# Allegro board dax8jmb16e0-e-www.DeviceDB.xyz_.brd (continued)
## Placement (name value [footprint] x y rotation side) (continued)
R623  33/F_4  [R0402]  49 29.29 270 top
R625  2.2K_2  [R0201]  78.52 125.46 270 top
R626  2.2K_2  [R0201]  77.76 125.46 270 top
R627  60.4/F_4  [R0402]  142.44 103.81 180 bottom
R628  4.7K/F_4  [R0402]  146.34 82.4 90 bottom
R629  *20K/F_4  [R0402]  144.94 82.83 180 bottom
R630  *8.25K/F_4  [R0402]  63.53 127.16 0 bottom
R632  *1K_1%_2  [R0201]  38.44 121.09 90 top
R633  *1K_1%_2  [R0201]  37.55 121.49 0 top
R634  *1K_1%_2  [R0201]  37.3 120.78 180 top
R635  *1K_1%_2  [R0201]  36.43 121.19 90 top
R637  *1K_1%_2  [R0201]  34.17 121.47 180 top
R638  *1K_1%_2  [R0201]  33.13 120.86 180 top
R639  *1K_1%_2  [R0201]  33 121.65 180 top
R640  *1K_1%_2  [R0201]  38.95 110.6 90 top
R641  *1K_1%_2  [R0201]  38.21 110.67 270 top
R642  *1K_1%_2  [R0201]  37.04 110.39 90 top
R643  *1K_1%_2  [R0201]  36.23 110.6 270 top
R644  *1K_1%_2  [R0201]  34.27 110.65 270 top
R645  *1K_1%_2  [R0201]  33.38 110.67 0 top
R646  *1K_1%_2  [R0201]  32.52 110.72 90 top
R647  *1K_1%_2  [R0201]  32.52 109.73 270 top
R648  *0_4  [R0402]  129.42 68.56 90 top
R649  10K_5%_2  [R0201]  154.82 96.73 270 bottom
R651  10K_5%_2  [R0201]  143.11 85.83 0 top
R652  100K_4  [R0402]  146.06 92.36 180 top
R653  100K_4  [R0402]  135.61 70.68 90 top
R654  *20K/F_4  [R0402]  134.56 71.76 270 top
R655  *0_2  [R0201]  132.24 75.43 180 bottom
R656  *0_2  [R0201]  149.21 69.53 180 top
R657  *0_2  [R0201]  125.89 76.36 270 bottom
R659  100K/F_4  [R0402]  153.7 92.03 90 top
R660  100K_4  [R0402]  146.92 69.65 180 top
R2800  240_4  [R0402]  81.95 39.48 90 top
R2801  *0_6/S  [S0603]  119.26 37.27 180 top
R2802  240_4  [R0402]  72.98 45.14 90 top
R2803  240_4  [R0402]  71.97 45.14 90 top
R2804  240_4  [R0402]  72.75 37.01 269.6 top
R2805  240_4  [R0402]  70.95 45.14 90 top
R2806  240_4  [R0402]  74 45.14 90 top
R2807  240_4  [R0402]  75.01 45.14 90 top
R2808  240_4  [R0402]  71.69 37.01 270 top
R2809  240_4  [R0402]  69.93 45.14 90 top
R2810  240_4  [R0402]  73.77 37.01 270 top
R2811  240_4  [R0402]  74.84 37.01 270 top
R2812  1K_1%_2  [R0201]  120.73 39.2 0 top
R2813  2/F_6  [R0603]  119.52 41.36 90 top
R2814  *10K_5%_2  [R0201]  113.11 39.78 180 top
R2815  *10K_5%_2  [R0201]  113.11 40.57 180 top
R2816  *10K_5%_2  [R0201]  92.67 36.91 0 top
R2817  1K_1%_2  [R0201]  120.73 38.46 180 top
R2818  24.9/F_4  [R0402]  117.92 43.11 270 top
R2819  10K_5%_2  [R0201]  114.66 39.78 180 top
R2820  10K_5%_2  [R0201]  114.66 40.57 180 top
R2821  10K_5%_2  [R0201]  92.67 37.7 180 top
R2822  *0_6/S  [S0603]  125.46 37.39 90 top
R2823  *10K_5%_2  [R0201]  190.1 41.25 270 top
R2824  10K_5%_2  [R0201]  190.86 41.84 270 top
R2825  *10K_5%_2  [R0201]  170.65 37.11 90 top
R2826  10K_5%_2  [R0201]  190.64 39.65 270 top
R2827  *10K_5%_2  [R0201]  190.99 40.95 0 top
R2828  10K_5%_2  [R0201]  169.73 37.62 0 top
R2829  240_4  [R0402]  148.78 37.83 270 top
R2830  240_4  [R0402]  147.56 45.12 90 top
R2831  240_4  [R0402]  150.99 45.12 90 top
R2832  240_4  [R0402]  149.84 45.12 90 top
R2833  240_4  [R0402]  150.68 41.61 180 top
R2834  240_4  [R0402]  147.71 37.83 270 top
R2835  240_4  [R0402]  146.41 45.12 90 top
R2836  240_4  [R0402]  150.5 37.93 270 top
R2837  240_4  [R0402]  151.95 38.08 0 top
R2838  240_4  [R0402]  148.7 45.12 90 top
R2839  1K_1%_2  [R0201]  121.83 39.6 180 top
R2840  1K_1%_2  [R0201]  121.83 38.84 0 top
R2841  2/F_6  [R0603]  121.04 41.36 90 top
R2842  24.9/F_4  [R0402]  122.33 41.79 90 top
R3300  10K_5%_2  [R0201]  14.72 100.26 270 top
R3301  10K/F_4  [R0402]  146.13 10.8 180 bottom
R3302  *10K/F_4  [R0402]  147.86 10.8 0 bottom
R3303  *0_4/S  [S0402]  147.86 11.77 180 bottom
R3304  *0_4/S  [S0402]  197.16 22.76 90 bottom
R3305  *0_4/S  [S0402]  174.05 24.9 270 bottom
R3306  *0_4/S  [S0402]  149.23 11.33 270 bottom
R3307  *0_4/S  [S0402]  155.46 21.09 270 bottom
R3309  10K_5%_2  [R0201]  125.59 122.99 0 top
R3310  *0_4  [R0402]  127.14 121.06 0 top
R3311  *0_4/S  [S0402]  48.5 95.28 90 top
R3312  *0_4/S  [S0402]  14.33 102.67 0 top
R3400  1K_1%_2  [R0201]  25.69 124.82 90 top
R3402  *0_4/S  [S0402]  25.79 123.42 90 top
R3404  100K_1%_2  [R0201]  24.6 121.34 90 top
R3405  1K_1%_2  [R0201]  39.61 126.29 270 top
R3408  *0_4/S  [S0402]  27.11 129.29 90 top
R3409  *0_4/S  [S0402]  28.13 129.29 90 top
R3410  100K_1%_2  [R0201]  31.99 122.41 270 top
R3411  *0_6/S  [S0603]  46.03 127.89 0 top
R3412  *100K_4  [R0402]  33.92 128.81 90 top
R3413  *100K_4  [R0402]  32.77 128.81 90 top
R3414  *1K_4  [R0402]  37.42 125.94 180 top
R3415  *1K_4  [R0402]  23.15 120.83 0 top
R3416  10_4  [R0402]  37.42 126.93 0 top
R3417  *0_5%_6/S  [S0603]  41.3 126.41 180 top
R3418  *0_5%_6/S  [S0603]  42.27 124.93 180 top
R3419  *0_5%_6/S  [S0603]  24.29 127.06 270 top
R3420  10K_5%_2  [R0201]  24.34 128.73 0 top
R3421  2.2K_2  [R0201]  32.67 130.66 90 top
R3422  2.2K_2  [R0201]  33.41 130.66 90 top
R3423  2K_1%_4  [R0402]  23.15 121.98 180 top
R3424  47K_1%_4  [R0402]  16.62 114.74 0 top
R3425  *0_4  [R0402]  45.32 124.52 180 top
R3428  470K_4  [R0402]  30.84 132.14 0 top
R3500  *150_5%_4  [R0402]  227.9 77.35 90 bottom
R3501  *150_5%_4  [R0402]  227.9 75.6 90 bottom
R3502  *150_5%_4  [R0402]  229.19 77.96 0 top
R3503  *150_5%_4  [R0402]  227.9 73.82 90 bottom
R3504  *4.7K_4  [R0402]  214.36 82.76 90 top
R3505  *4.7K_4  [R0402]  214.36 85.07 90 top
R3506  *4.7K_4  [R0402]  211.26 87.51 90 bottom
R3507  *4.7K_4  [R0402]  213 83.46 0 top
R3508  *4.7K_4  [R0402]  213.37 85.07 270 top
R3509  5.9K_1%_4  [R0402]  215.35 85.07 270 top
R3510  2.2K_2  [R0201]  227.87 62.29 90 bottom
R3511  2.2K_2  [R0201]  226.73 62.29 90 bottom
R3512  2.2K_2  [R0201]  213.47 94.01 270 top
R3513  2.2K_2  [R0201]  212.4 94.01 270 top
R3600  *0_4/S  [S0402]  225.67 21.64 0 top
R3601  BLM15BB121SN1D(120,300)  [R0402]  225.61 13.39 0 top
R3602  BLM15BB121SN1D(120,300)  [R0402]  225.76 12.43 0 top
R3606  *0_4/S  [S0402]  214.03 14.03 0 top
R3607  22/F_4  [R0402]  212.63 13.47 270 top
R3608  30/F_4  [R0402]  223.86 13.19 0 top
R3609  30/F_4  [R0402]  224.01 12.22 0 top
R3610  200K_4  [R0402]  213.95 7.85 270 top
R3611  22/F_4  [R0402]  213.47 10.17 180 top
R3612  100K_4  [R0402]  222.77 6.61 0 top
R3613  100K_4  [R0402]  216.93 7.57 180 top
R3614  200K_4  [R0402]  219.38 6.85 180 top
R3615  *0_4/S  [S0402]  214.46 11.56 270 top
R3616  1K_1%_2  [R0201]  208.99 7.09 270 top
R3617  1K_1%_2  [R0201]  211.74 6.91 270 top
R3618  *0_8/S  [S0805]  221.04 12.12 0 bottom
R3619  2.2K_2  [R0201]  223.68 11.21 180 top
R3620  100K_4  [R0402]  216.01 16.41 180 top
R3621  *0_4/S  [S0402]  216.01 17.38 0 top
R3622  *0_4  [R0402]  216.8 24.08 0 top
R3623  *10K_1%_4  [R0402]  211.72 18.27 90 top
R3624  *0_4/S  [S0402]  216.81 6.61 180 top
R3627  *0_4/S  [S0402]  227.62 23.86 90 bottom
R4000  2.49K/F_4  [R0402]  196.32 63.05 270 top
R4001  1K_4  [R0402]  186.04 67.72 180 top
R4002  1M_4  [R0402]  192.9 61.52 270 top
R4003  4.3K/F_4  [R0402]  185.96 70.54 90 top
R4004  15K/F_4  [R0402]  189.31 68.56 0 top
R4005  2K/F_4  [R0402]  186.95 70.54 90 top
R4006  *0_4  [R0402]  189.06 72.6 90 top
R4007  330/F_4  [R0402]  227.69 93.15 0 top
R4008  330/F_4  [R0402]  227.95 92.13 180 top
R4012  *0_6/S  [S0603]  231.21 106.67 90 bottom
R4013  *0_6/S  [S0603]  230.34 81.97 180 bottom
R4014  75/F_4  [R0402]  223.63 65.08 180 bottom
R4015  75/F_4  [R0402]  223.63 68.26 180 bottom
R4016  75/F_4  [R0402]  223.58 70.08 180 bottom
R4017  75/F_4  [R0402]  223.4 75.21 90 bottom
R4018  *0_4/S  [S0402]  191.91 60.89 90 top
R4101  100K_1%_2  [R0201]  181.69 89.08 0 top
R4103  *0_4  [R0402]  182.35 87.13 180 top
R4104  10K_5%_2  [R0201]  171.15 89.46 270 top
R4105  *0_4/S  [S0402]  174.79 88.58 180 top
R4106  10K_5%_2  [R0201]  145.27 94.26 180 bottom
R4107  100K_1%_2  [R0201]  171.89 89.46 270 top
R4108  100K_1%_2  [R0201]  166.02 83.42 0 top
R4109  *0_4/S  [S0402]  159.01 81.13 0 bottom
R4110  *0_4/S  [S0402]  159.01 80.17 0 bottom
R4111  100K_1%_2  [R0201]  166.02 82.66 180 top
R4113  *0_5%_4  [R0402]  170.16 95.69 90 bottom
R4114  *0_5%_4  [R0402]  171.18 95.69 90 bottom
R4115  *0_5%_4  [R0402]  171.38 92.74 90 bottom
R4116  1K_1%_2  [R0201]  143.95 94.37 90 bottom
R4117  *10K_5%_2  [R0201]  172.6 89.46 90 top
R4118  22/F_4  [R0402]  168.89 90.02 180 top
R4119  22/F_4  [R0402]  162.43 90.14 180 top
R4120  *0_4  [R0402]  173.34 92.94 90 bottom
R4122  *0_4/S  [S0402]  164.19 83.37 180 top
R4123  *0_4/S  [S0402]  159.78 86.32 0 top
R4136  *4.7K/F_4  [R0402]  177.5 85.35 0 top
R4137  10K/F_4  [R0402]  175.75 85.43 0 top
R4138  *75K_1%_4  [R0402]  175.27 86.54 180 top
R4139  75K/F_4  [R0402]  183.24 89.08 180 top
R4140  *0_4  [R0402]  174.81 87.58 0 top
R4141  100K_1%_4  [R0402]  179.23 85.35 180 top
R4142  *0_6/S  [S0603]  179.31 92.61 0 top
R4143  20K/F_4  [R0402]  167.54 90.1 90 top
R4144  *20K/F_4  [R0402]  170.62 90.88 0 top
R4145  *0_4/S  [S0402]  162.79 87.32 180 top
R4146  *200K_1%_4  [R0402]  162.81 86.08 0 top
R4147  10K_5%_2  [R0201]  144.25 86.67 270 top
R4200  *0_6/S  [S0603]  189.31 81.03 0 top
R4202  *0_4/S  [S0402]  204.81 76.64 180 top
R4203  10K_5%_2  [R0201]  191.04 82.35 270 bottom
R4209  *0_4/S  [S0402]  193.25 82.76 90 bottom
R4210  *10K_5%_2  [R0201]  191.93 82.35 270 bottom
R4212  0_4*  [R0402]  190.05 72.6 270 top
R4213  *0_4  [R0402]  191.19 83.44 90 top
R4214  *10K_5%_2  [R0201]  193.78 71.94 270 top
R4215  *0_4  [R0402]  195.11 78.16 270 top
R4222  *47K/F_4  [R0402]  204.71 66.1 180 bottom
R4223  *0_4  [R0402]  218.3 57.59 0 bottom
R4225  *100K_4  [R0402]  206.22 66.45 90 bottom
R4235  100K_1%_2  [R0201]  194.55 79.43 0 top
R4240  *100K_1%_2  [R0201]  198.48 79.81 270 top
R4242  *0_4  [R0402]  204.81 77.68 0 top
R4245  *0_4/S  [S0402]  200.4 82.46 180 bottom
R4246  *47K/F_4  [R0402]  204.68 78.75 180 top
R4247  *0_4/S  [S0402]  189.47 76.38 0 top
R4248  *0_4/S  [S0402]  189.47 75.42 0 top
R4249  10K_5%_2  [R0201]  207.15 65.94 45 top
R4250  10K_5%_2  [R0201]  205.88 64.01 270 top
R4251  0_4  [R0402]  205.78 63.01 180 top
R4252  0_4  [R0402]  209.18 60.13 270 top
R4253  0_4  [R0402]  205.77 62.03 180 top
R4300  *0_4  [R0402]  204.3 7.37 90 bottom
R4301  0_4  [R0402]  203.98 14.01 270 bottom
R4302  0_4  [R0402]  208.31 16.21 0 top
R4303  *0_5%_4  [R0402]  203.78 15.44 180 bottom
R4304  0_4  [R0402]  208.31 17.48 0 top
R4305  10K/F_4  [R0402]  206.97 21.19 0 top
R4306  *0_4  [R0402]  206.97 22.15 180 top
R4307  *0_4  [R0402]  206.61 23.55 90 top
R4308  0_4  [R0402]  210.36 12.04 0 top
R4309  0_4  [R0402]  210.36 13.06 0 top
R4310  *0_6/S  [S0603]  203.34 9.63 270 bottom
R4700  1M/F_4  [R0402]  214.49 54.64 0 top
R4702  *0_4  [R0402]  215.48 49.84 180 top
R4704  2.2K_2  [R0201]  202.96 62.55 180 top
R4705  2.2K_2  [R0201]  202.96 61.82 180 top
R4706  100K_1%_2  [R0201]  145.02 87.18 180 bottom
R4707  *300_4  [R0402]  205.22 45.7 270 top
R4708  300_4  [R0402]  206.18 45.67 270 top
R4709  4.7_5%_4  [R0402]  201.97 59.59 270 top
R4710  300_4  [R0402]  197.54 42.52 0 top
R4711  4.7_5%_4  [R0402]  204.98 59.59 270 top
R4712  300_4  [R0402]  193.63 49.28 180 top
R4713  4.7_5%_4  [R0402]  204 59.59 270 top
R4714  43_4  [R0402]  213.34 52.48 0 top
R4715  *0_4/S  [S0402]  195.16 55.84 0 top
R4716  *0_6/S  [S0603]  200.92 45.22 225 top
R4717  10K_5%_2  [R0201]  197.09 48.29 0 top
R4718  10K_5%_2  [R0201]  197.11 47.05 0 top
R4719  2.2/F_6  [R0603]  197.75 40.7 270 top
R4720  10K_5%_2  [R0201]  216.11 47.17 180 top
R4721  10K_5%_2  [R0201]  211.21 48.71 180 top
R4722  10K_5%_2  [R0201]  216.11 47.91 180 top
R4723  2.2/F_6  [R0603]  213.8 62.13 0 top
R4724  2.2K_2  [R0201]  198.05 56.34 270 top
R4725  2.2K_2  [R0201]  197.34 56.34 270 top
R4726  2.2K_2  [R0201]  213.22 53.88 270 top
R4727  2.2K_2  [R0201]  214.66 53.78 0 top
R4728  10K_5%_2  [R0201]  212.71 54.89 180 top
R4729  *10K_5%_2  [R0201]  213.01 59.11 0 top
R4730  100K_4  [R0402]  214.38 58.98 0 top
R4731  2.2/F_6  [R0603]  194.84 59.7 0 top
R4732  10K_5%_2  [R0201]  185.48 58.3 0 top
R4733  10K_5%_2  [R0201]  185.63 59.97 270 top
R4734  10K_5%_2  [R0201]  180.35 58.91 180 top
R4735  10K_5%_2  [R0201]  179.31 59.24 0 top
R4736  2.2/F_6  [R0603]  195.72 43.9 270 top
R4737  *0_4  [R0402]  182.94 61.93 0 top
R4738  *0_4  [R0402]  182.91 58.6 0 top
R4739  1K_1%_2  [R0201]  200.95 59.21 270 top
R4740  100K_1%_2  [R0201]  197.01 50.09 180 top
R4741  1K_1%_2  [R0201]  199.27 46 90 top
R4742  470K_4  [R0402]  207.53 46.06 180 top
R4743  *100K_1%_2  [R0201]  213.24 50.4 0 top
R4744  *10K_5%_2  [R0201]  211.18 54.67 180 top
R4745  100K_1%_2  [R0201]  196.05 50.63 90 top
R4746  *1K_1%_2  [R0201]  215.91 48.77 270 top
R4747  20K/F_4  [R0402]  213.75 49.54 0 top
R4748  *10K_5%_2  [R0201]  211.84 51.69 0 top
R4749  *1K_1%_2  [R0201]  196.55 46.26 0 top
R4750  100K_1%_2  [R0201]  212.94 57.74 90 top
R4751  *1K_1%_2  [R0201]  197.85 54.11 0 top
R4752  100K_1%_2  [R0201]  197.01 50.96 0 top
R4753  100K_1%_2  [R0201]  197.85 54.84 180 top
R4754  47_4  [R0402]  195.77 52.53 270 top
R4755  *0_4  [R0402]  196.4 54.26 0 top
R4756  100K_1%_2  [R0201]  209.43 44.53 90 top
R4757  4.7_5%_4  [R0402]  202.99 59.59 270 top
R4760  10K_5%_2  [R0201]  196.58 55.15 180 top
R4761  *0_4/S  [S0402]  183.17 54.74 270 top
R4762  *0_4/S  [S0402]  213.32 55.73 180 top
R4763  10K_5%_2  [R0201]  211.46 55.43 0 top
R4764  10K_5%_2  [R0201]  200.19 59.19 270 top
R4765  *0_4/S  [S0402]  210.42 45.98 180 top
R4766  300_4  [R0402]  198.03 46.06 0 top
R4767  *0_4/S  [S0402]  193.61 50.25 180 top
R4768  100K_4  [R0402]  187.16 58.4 0 top
R4769  *10K_5%_2  [R0201]  72.45 125.61 0 top
R4770  2.2K_2  [R0201]  210.04 60.64 270 top
R4771  2.2K_2  [R0201]  204.13 61.89 0 top
R4772  2.2K_2  [R0201]  204.55 63.28 270 top
R4773  *4.7_5%_4  [R0402]  195.24 60.97 0 top
R4774  *4.7_5%_4  [R0402]  211.72 59.49 270 top
R5000  *0_4/S  [S0402]  39.3 54.67 0 top
R5001  *0_4/S  [S0402]  39.3 53.68 0 top
R5002  470/F_4  [R0402]  41.86 53.35 0 top
R5003  200/F_4  [R0402]  41.87 51.42 0 top
R5004  200/F_4  [R0402]  41.87 50.45 0 top
R5005  470/F_4  [R0402]  41.51 55.68 90 top
R5006  200/F_4  [R0402]  41.87 54.34 0 top
R5007  470/F_4  [R0402]  41.87 52.38 0 top
R5008  *0_4/S  [S0402]  38.68 50.77 270 top
R5009  20K/F_4  [R0402]  46.8 53.29 270 top
R5010  *20K/F_4  [R0402]  46.9 50.81 180 top
R5011  100K_1%_2  [R0201]  139.58 24.67 0 bottom
R5012  47K/F_4  [R0402]  45.88 57.26 180 top
R5013  47K/F_4  [R0402]  44.08 57.26 0 top
R5014  470/F_4  [R0402]  42.6 56.32 270 top
R5015  100K/F_4  [R0402]  48.4 57.28 0 top
R5016  *10K_10P8R_6  [10P8R]  39.84 43.01 0 top
R5100  150K/F_4  [R0402]  172.86 67.44 270 top
R5101  10K_5%_2  [R0201]  174.48 70.97 270 top
R5102  *0_4  [R0402]  175.32 69.55 90 top
R5103  *0_4/S  [S0402]  171.36 66.55 180 top
R5104  4.7K/F_4  [R0402]  165.95 72.24 270 top
R5105  *0_4  [R0402]  164.96 72.47 270 top
R5106  *10K/F_4  [R0402]  171.36 67.57 0 top
R5107  4.7K/F_4  [R0402]  166.23 70.49 90 top
R5108  *51K_4  [R0402]  169.4 65.26 0 top
R5109  *10K/F_4  [R0402]  166.94 66.48 270 top
R5110  22/F_4  [R0402]  176.28 69.55 270 top
R5111  22/F_4  [R0402]  174.89 74.22 0 top
R5112  22/F_4  [R0402]  177.53 72.45 270 top
R5205  *0_4/S  [S0402]  187.79 11.66 135 bottom
R5206  *0_4/S  [S0402]  187.1 10.98 135 bottom
R5207  10K_5%_2  [R0201]  176.69 16.62 180 bottom
R5300  *0_4/S  [S0402]  64.93 30.43 90 top
R5301  *0_4  [R0402]  70.82 21.8 0 top
R5302  *0_4/S  [S0402]  68.84 21.77 180 top
R5303  *0_5%_4  [R0402]  75.52 128.66 180 top
R5304  *0_5%_4  [R0402]  74.91 126.27 90 top
R5305  *0_5%_4  [R0402]  75.69 130.69 270 top
R5400  10K_5%_2  [R0201]  48.62 69.14 0 top
R5401  22/F_4  [R0402]  48.47 70.29 0 top
R5402  10K_5%_2  [R0201]  47.48 65.97 180 top
R5403  150/F_4  [R0402]  42.76 111.69 180 bottom
R5404  *470K/J_4  [R0402]  35.67 114.76 180 bottom
R5405  10K/F_4  [R0402]  170.01 100.36 180 top
R5406  33.2K/F_4  [R0402]  36.48 112.81 270 bottom
R5407  2.2K_2  [R0201]  164.73 99.29 180 top
R5408  2.2K_2  [R0201]  165.97 98.63 0 top
R5600  *0_4/S  [S0402]  163.81 67.95 90 top
R5601  4.7K_5%_4  [R0402]  177.97 76.92 90 top
R5602  *2.55K/F_4  [R0402]  175.78 71.35 90 top
R5603  *3.3K/F_4  [R0402]  177.04 79.53 270 top
R5604  *3.3K/F_4  [R0402]  169.65 75.88 90 top
R5605  *0_4  [R0402]  171.86 75.88 90 top
R5606  22/F_4  [R0402]  174.35 69.55 90 top
R5607  22/F_4  [R0402]  174.4 75.6 270 top
R5608  22/F_4  [R0402]  177.15 74.22 270 top
R5609  15_4  [R0402]  170.72 75.88 270 top
R5610  15_4  [R0402]  174.29 79.84 180 top
R5611  22/F_4  [R0402]  176.97 76.92 270 top
R5612  *22/F_4  [R0402]  168.24 76.3 180 top
R5613  *22/F_4  [R0402]  175.67 79.93 90 top
R5614  22/F_4  [R0402]  178.96 76.04 270 top
R5700  *0_4  [R0402]  221.68 53.68 180 bottom
R5701  *0_4  [R0402]  221.68 54.69 180 bottom
R5702  *0_4  [R0402]  221.31 33.36 180 top
R5703  *0_4  [R0402]  221.31 32.34 180 top
R5800  4.99K/F_4  [R0402]  209.79 114.35 0 top
R5801  4.7K_5%_4  [R0402]  208.77 105.59 270 top
R5802  2.2K_2  [R0201]  204.43 104.3 0 top
R5803  2.2K_2  [R0201]  204.28 105.26 90 top
R5804  *4.7K_4  [R0402]  209.79 115.37 180 top
R5805  4.7K_5%_4  [R0402]  208.06 114.66 270 top
R5806  *20K/F_4  [R0402]  210.8 110.04 0 bottom
R5807  2.2K_2  [R0201]  201.15 103.31 0 top
R5808  2.2K_2  [R0201]  200.52 104.45 270 top
R5809  *0_4  [R0402]  199.14 99.12 0 top
R5810  100K_5%_4  [R0402]  206.99 105.11 270 top
R5811  100K_1%_4  [R0402]  205.98 105.11 90 top
R6100  *10K/F_4  [R0402]  190.13 103.76 180 top
R6101  *2.2K_4  [R0402]  195.31 112.71 0 top
R6102  52.3K_1%_4  [R0402]  196.65 113.82 180 top
R6103  10K/F_4  [R0402]  187.33 104.73 0 top
R6104  100K/F_4  [R0402]  194.04 111.69 180 top
R6105  374K_1%_4  [R0402]  193.51 113.09 180 top
R6106  *4.7K_4  [R0402]  182.91 113.54 90 top
R6107  *4.7K_4  [R0402]  184.29 113.24 180 top
R6108  4.7K_5%_4  [R0402]  184.23 104.96 270 top
R6109  *0_4/S  [S0402]  189.95 102.8 0 top
R6110  *0_4/S  [S0402]  185.76 114.03 270 top
R6111  *0_4/S  [S0402]  193.15 106.1 90 top
R6112  *0_4/S  [S0402]  194.27 97.08 270 top
R6113  100K_4  [R0402]  190.13 104.73 0 top
R6114  *0_4/S  [S0402]  187.46 114.36 0 top
R6115  *0_6/S  [S0603]  182.61 107.14 270 top
R6116  10K/F_4  [R0402]  185.2 103.36 180 top
R6117  *0_4  [R0402]  204.05 64.9 270 top
R6118  *0_4  [R0402]  202.67 64.45 180 top
R6119  *0_4/S  [S0402]  217.41 60.69 270 bottom
R6120  *0_4/S  [S0402]  218.42 60.69 270 bottom
R6211  330T30_4  [R0402]  61.58 32.12 90 bottom
R6212  330T30_4  [R0402]  62.72 32.12 90 bottom
R6213  10K/F_4  [R0402]  59.34 29.85 90 bottom
R6214  *0_4/S  [S0402]  63.99 32.1 270 bottom
R6215  *0_4/S  [S0402]  65.13 32.1 270 bottom
R6300  *2M_4  [R0402]  228.03 113.71 180 top
R6301  *2M_4  [R0402]  228.03 114.77 180 top
R6302  *0_6/S  [S0603]  225.41 103.56 270 top
R6303  *0_6/S  [S0603]  225.41 106.23 90 top
R6315  *0_4/S  [S0402]  218.8 112.91 0 top
R6316  *0_4/S  [S0402]  218.8 111.89 0 top
R6317  *0_4/S  [S0402]  218.8 109.91 0 top
R6318  *0_4/S  [S0402]  218.8 110.93 0 top
R6319  10K/F_4  [R0402]  218.52 94.03 0 top
R6320  14.3K_1%_4  [R0402]  220.18 93.91 90 top
R6322  10K/F_4  [R0402]  226.55 96.75 270 top
R6323  1M_1%_4  [R0402]  225.92 95.31 180 top
R6324  470K_5%_4  [R0402]  225.92 94.29 0 top
R6325  *220K_5%_2  [R0201]  212.03 109.61 90 top
R6326  *220K_5%_2  [R0201]  212.03 108.46 270 top
R6327  *220K_5%_2  [R0201]  229.88 110.01 270 top
R6328  *220K_5%_2  [R0201]  229.88 111.03 90 top
R6329  220K_5%_2  [R0201]  230.62 112.4 90 top
R6330  220K_5%_2  [R0201]  230.62 111.38 270 top
R6331  220K_5%_2  [R0201]  211.94 112.44 270 top
R6332  220K_5%_2  [R0201]  211.94 113.83 90 top
R6832  *0_4  [R0402]  41.87 49.36 180 top
R7500  2.2K_5%_4  [R0402]  52.18 61.4 0 top
R7501  10K_1%_4  [R0402]  50.53 59.24 180 top
R7502  *10K_2  [R0201]  52.38 57.74 180 top
R7503  *10K_2  [R0201]  54.11 57.71 0 top
R7504  470K_4  [R0402]  49.51 58.25 0 top
R7505  470K_4  [R0402]  45.7 62.16 180 top
R7506  *0_4  [R0402]  47.48 62.16 0 top
R7507  2.2K_2  [R0201]  53.58 61.4 270 top
R7508  *0_4  [R0402]  50.4 61.4 0 top
R7509  *0_4/S  [S0402]  50.4 60.38 180 top
R7510  *0_4  [R0402]  47.48 58.6 0 top
R7600  *10K_4  [R0402]  44.12 23.32 0 top
R7610  49.9K_1%_4  [R0402]  47.3 34.6 90 top
R7611  7.5K_1%_4  [R0402]  44.33 36.15 0 top
R7613  10K_4  [R0402]  45.83 25.94 0 top
R7615  *0_4/S  [S0402]  44.12 22.31 180 top
R7616  100/F_4  [R0402]  11.67 107.29 270 top
R7617  1M/F_4  [R0402]  15.55 109.53 90 top
R7618  2M_4  [R0402]  14.51 109.53 270 top
R7619  *0_4  [R0402]  15.5 106.1 90 top
R7621  10K_4  [R0402]  46.34 34.6 270 top
R7622  *0_4/S  [S0402]  47.28 27.56 180 top
R7623  *0_4/S  [S0402]  47.28 28.53 180 top
R7624  *0_4/S  [S0402]  47.28 29.49 180 top
R7625  33/F_4  [R0402]  39.19 29.54 0 bottom
R7626  *0_4/S  [S0402]  49.13 30.92 180 top
R7627  *0_4/S  [S0402]  47.33 31.45 180 top
R7628  *10K/F_4  [R0402]  64.32 125.48 90 bottom
R7629  *2.2K_2  [R0201]  77.69 125.9 270 bottom
R7630  *2.2K_2  [R0201]  70.54 125.37 0 bottom
R7633  *0_4  [R0402]  73.16 128.1 90 top
R7634  0_4  [R0402]  38.67 27.77 270 top
R7635  0_4  [R0402]  39.66 27.77 270 top
R7636  0_4  [R0402]  30.97 22.15 0 top
R7637  0_4  [R0402]  30.74 23.12 0 top
R7638  33_4  [R0402]  40.93 29.69 0 bottom
R7639  33_4  [R0402]  41.37 32.1 0 bottom
R7640  33_4  [R0402]  36.91 29.9 270 bottom
R7641  33_4  [R0402]  36.94 29.19 270 top
R7700  *0_4  [R0402]  150.76 72.67 270 bottom
R7701  *0_4  [R0402]  159.7 78.8 270 bottom
R7702  *0_4  [R0402]  151.72 72.67 270 bottom
R7703  *0_4  [R0402]  157.03 77.4 0 bottom
R7704  *0_4  [R0402]  154.42 72.24 270 bottom
R7705  *0_4  [R0402]  154.97 74.35 90 bottom
R7706  0_4  [R0402]  156.04 72.22 270 bottom
R7707  0_4  [R0402]  154.42 76.13 270 bottom
R7708  0_4  [R0402]  153.07 72.47 0 bottom
R7709  0_4  [R0402]  158.35 78.67 0 bottom
R7710  0_4  [R0402]  153.07 73.44 0 bottom
R7711  0_4  [R0402]  160.71 78.8 270 bottom
R7712  *0_4  [R0402]  162.97 65.49 180 top
R7713  49.9K_1%_4  [R0402]  156.62 78.36 0 bottom
R7714  49.9K_1%_4  [R0402]  153.78 78.03 180 bottom
R7716  *51_4  [R0402]  39.3 121.44 90 top
R7717  0_4  [R0402]  31.15 121.47 270 top
R7718  1K_1%_2  [R0201]  30.31 121.34 90 top
R7719  1K_1%_2  [R0201]  30.44 107.93 270 top
R7720  1K_1%_2  [R0201]  32.14 121.42 90 top
R7722  *0_4  [R0402]  40.32 121.44 90 top
R7723  0_5%_4  [R0402]  31.33 109.12 270 top
R7724  1K_1%_2  [R0201]  172.96 76.38 180 top
R7725  150_5%_4  [R0402]  29.45 121.32 90 top
R7726  1K_1%_2  [R0201]  38.46 122.69 0 top
R7727  1K_1%_2  [R0201]  176.39 72.83 180 top
R7728  1.5K_5%_4  [R0402]  27.41 121.72 90 top
R7729  *51_4  [R0402]  28.88 106.06 180 top
R7730  0_4  [R0402]  217.41 58.93 90 bottom
R7731  0_4  [R0402]  218.42 58.93 90 bottom
R7732  0_4  [R0402]  170.79 13.78 180 bottom
R7733  0_4  [R0402]  173.24 14.18 90 bottom
R7734  0_4  [R0402]  172.22 14.18 90 bottom
R7735  *51_4  [R0402]  21.45 110.98 270 top
R7736  51_4  [R0402]  101.94 106.25 90 bottom
R7737  51_4  [R0402]  102.8 108.46 90 bottom
R7738  51_4  [R0402]  104 106.23 90 bottom
R9647  10K/F_4  [R0402]  60.33 29.85 90 bottom
R9648  240_4  [R0402]  160.64 37.37 270 top
R9649  10M_4  [R0402]  60.2 65.22 270 top
RR9700  *HCB1608KF-121T30  [R0603]  187.7 23.63 0 top
TP400  *  [TP2050]  94.67 108.41 180 bottom
TP401  *  [TP2050]  107.5 105.97 180 bottom
TP402  *  [TP2050]  94.7 107.14 180 bottom
TP404  *  [TP2050]  141.53 75.65 180 bottom
TP406  *  [TP2650]  129.14 76 0 top
TP410  *  [TP2050]  145.4 89.46 180 bottom
TP417  *  [TP2050]  112.07 107.96 180 bottom
TP418  *PAD  [TP2650]  91.47 74.1 180 bottom
TP421  *  [TP2050]  144.81 80.22 180 bottom
TP422  *  [TP2050]  128.17 74.67 0 top
TP423  *  [TP2050]  139.58 72.77 180 bottom
TP424  *  [TP2050]  138.46 73.39 180 bottom
TP425  *  [TP2050]  144.13 86.92 180 bottom
TP426  *  [TP2650]  130.64 74.27 0 top
TP427  *  [TP2050]  145.53 87.94 180 bottom
TP428  *  [TP2050]  155.94 78.92 0 top
TP2800  *PAD  [TP2650]  168.66 37.65 0 top
TP2801  *PAD  [TP2650]  90.97 37.27 0 top
TP2802  *PAD  [TP2650]  91.55 44.51 0 top
TP2803  *PAD  [TP2650]  168.84 42.17 0 top
TP4000  *  [TP2050]  192.84 63.86 270 top
TP4001  *  [TP2050]  191.12 63.39 180 top
TP4002  *  [TP2050]  194.09 63.53 180 top
TP4100  *  [TP2050]  175.14 92.18 180 bottom
TP4101  *  [TP2050]  176.03 93.22 180 bottom
TP4102  *  [TP2050]  176.94 92.26 180 bottom
TP4200  *  [TP2050]  207.75 63.33 180 bottom
TP4300  *  [TP2050]  205.15 20.78 180 bottom
TP4700  *  [TP2650]  214.79 48.67 0 top
TP4701  *  [TP2650]  215.11 56.87 0 top
TP4702  *  [TP2650]  214.36 57.97 0 top
TP4703  *  [TP2650]  212.02 57.76 0 top
TP4704  *  [TP2650]  215.76 57.97 0 top
TP4706  *  [TP2650]  208.59 44.66 0 top
TP4707  *  [TP2650]  194.8 58.58 0 top
TP4710  *  [TP2650]  213.29 48.57 0 top
TP5100  *  [TP2675]  153.78 74.48 0 top
TP5300  *  [TP2650]  67.29 26.24 0 top
TP5600  *  [TP2675]  167.19 79.54 180 bottom
TP5601  *  [TP2675]  180.84 81.1 180 bottom
TP5602  *  [TP2675]  180.81 79.17 180 bottom
TP5603  *  [TP2675]  168.81 78.31 180 bottom
TP5800  *  [TP2050]  203.13 111.49 0 top
TP5801  *  [TP2050]  203.16 109.94 0 top
TP6100  *  [TP2050]  183.83 114.1 0 top
TP6101  *  [TP2050]  210.09 79.25 0 top
TP6102  *  [TP2050]  185.3 106.46 0 top
TP6103  *  [TP2050]  184.62 112.18 0 top
TP6104  *  [TP2050]  184.77 110.77 0 top
TP6105  *  [TP2050]  192.24 105.01 0 top
TP7606  *  [TP2050]  29.3 26.08 0 top
TP7607  *  [TP2050]  28.01 26.07 0 top
TP7608  *  [TP2050]  28.18 24.69 0 top
TP7609  *  [TP2050]  31.39 23.94 0 top
TP7700  *TP  [TP2050]  39.99 110.65 0 top
TP8200  *TP  [TP2050]  127.26 27.69 180 bottom
TP8201  *TP  [TP2050]  129.47 21.49 180 bottom
TP8202  *TP  [TP2050]  127.54 18.67 180 bottom
U400  *CFL_U_43E_1528P_0p7  [BGA1528-INTEL-WHL-U]  116.45 90.89 0 bottom
U401  *MC74VHC1G08DFT2G  [SOT353-1-2_125-65-5P]  127.8 66.71 270 top
U402  MC74VHC1G08DFT2G  [SOT353-1-2_125-65-5P]  128.99 61.78 90 top
U3400  G5245AT11U  [SOT23-5-2_8-95-5P-G708]  34.65 123.6 180 top
U3500  G5250Q1T73U  [SOT23-2_8-95-3P-1_45H]  225.03 71.68 90 bottom
U3501  PS8203  [TQFN32-3X6-4-41P-0_8H]  213.37 89.62 270 top
U3600  ALC3247-CG  [QFN40-5X5-4-41P-SMB349NT]  219.18 12.53 270 top
U4000  RTL8111HSH-CG  [QFN32-4X4-4-33P-0_9H]  194.93 67.11 90 top
U4001  NS892407  [TRF-N1010G-25P]  216.39 70.67 90 bottom
U4100  G517H1T11U  [SOT23-5-2_8-95-5P-G708]  182.93 91.24 180 top
U4201  74AUP1G97GM  [SOT363-2_1-65-6P]  196.83 78.44 270 top
U4202  NL17SZ08DFT2G  [SOT353-1-2_125-65-5P]  205.22 72.07 0 top
U4700  SN74LVC2G07DCKR  [SC70-2_1-65-6P]  182.89 60.25 0 top
U4701  NPCX797HA0BX  [BGA144-NUVOTON-NPCX797H]  204.58 52.63 0 top
U5100  SLB 9670VQ2.0 FW7.83  [QFN32-5X5-5-33P-SLB9645VQ]  169.88 71.48 270 top
U5300  HP2DCTR  [LGA12-2X2-5]  69.48 23.78 0 top
U5301  *HP2DCTR  [LGA12-2X2-5-HP2DCTR]  73.47 130.66 0 top
U5400  EMC1412-1-ACZL-TR  [MSOP8-4_9-65]  165.08 101.4 90 top
U5401  G708T1U  [SOT23-5-2_8-95-5P-G708]  39.48 113.67 180 bottom
U5600  BIOS Socket  [50951-0084N-001-8P-SOCKET]  173.2 76.33 180 bottom
U5700  PUSB3FR4  [UDFN10-2_5X1-5]  224.71 30.95 270 top
U5701  G517H1T11U  [SOT23-5-2_8-95-5P-G708]  221.65 39.25 0 bottom
U5702  PUSB3FR4  [UDFN10-2_5X1-5]  224.39 51.49 270 bottom
U5800  PS8743A  [QFN40-6X4-4-41P-0_8H]  206.36 109.78 180 top
U5801  G517H1T11U  [SOT23-5-2_8-95-5P-G708]  200.57 101.25 0 top
U6100  CYPD5125-40LQXIT  [QFN40-6X6-5-41P-0_6H]  189.11 109.78 270 top
U6300  PUSB3FR4  [UDFN10-2_5X1-5]  222.06 111.99 90 top
U6301  PUSB3FR4  [UDFN10-2_5X1-5]  230.39 110.7 90 bottom
U6302  NX5P3290AUKZ  [BGA16-NXP-NX5P3290A]  222.23 96.96 0 top
U6303  PUSB3FR4  [UDFN10-2_5X1-5]  227.97 111.78 270 top
U7500  SLG4E42033VTR  [QFN8-1_2X1-4]  53.58 59.24 180 top
U7600  BH28PQ10LN-A1-0-TR  [QFN28-4X4-4-29P-ANX7411]  43.42 30.16 90 top
U7601  *G517B1T11U  [SOT23-5-2_8-95-5P-G708]  67.12 124.77 0 bottom
VC3500  *TVM0G5R5M220R  [C0402]  230.95 61.37 180 top
VC5700  *AVLC5S_4  [C0402]  224.57 34.07 0 bottom
VC5701  *AVLC5S_4  [C0402]  220.71 41.99 270 bottom
VC5702  *AVLC5S_4  [C0402]  222.06 48.21 90 bottom
Y400  24MHZ/10ppm  [XTL-2X1_6-1_35X1_05]  150.22 100.98 270 bottom
Y401  32.768KHZ/20ppm  [XTL-3_2X1_5-2_5-SMT]  154.01 81.85 180 top
Y4000  25MHZ/30ppm  [XTL-2_05X1_65-1_4X1_1-0_6H]  189.09 61.6 180 top

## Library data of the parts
C400-C405 C407 C409 C416-C422 C424-C478 C481-C483 C485 C486 C490-C497 C508-C510 C518-C541 C546-C641 C2800-C2857 C3300 C3301 C3401-C3424 C3500-C3520 C3601 C3603 C3608-C3611 C3613 C3615-C3640 C4000-C4024 C4035-C4037 C4100-C4102 C4104-C4107 C4200-C4205 C4207-C4211 C4222 C4236-C4238 C4300-C4318 C4400-C4407 C4700-C4706 C4708 C4710-C4723 C4726 C4727 C4729 C5000 C5001 C5100-C5104 C5205 C5206 C5300-C5304 C5400-C5406 C5600 C5601 C5700-C5704 C5707-C5712 C5800-C5826 C6100-C6108 C6202-C6206 C6302 C7500 C7600-C7618 C7620 C7627-C7629 C7700-C7702 C7800-C7874 EC2800-EC2823 EC3400 EC3600-EC3603 EC3605-EC3613 EC4300 EC9700 PC8100-PC8105 PC8200 PC8201 PC8203-PC8206 PC8209-PC8213 PC8215 PC8217-PC8224 PC8600-PC8606 PC8608-PC8614 PC8617 PC8621-PC8627 PC8629-PC8634 PC8638 PC8726 PC8727 PC8800-PC8808 PC8812-PC8814 PC8816 PC8817 PC8900 PC8901 PC8907 PC8908 PC8911 PC8913-PC8915 PC8921 PC8924 PC8926 PC9002-PC9004 PC9015 PC9017-PC9019 PC9025 PC9027-PC9032 PC9034 PC9200 PC9207-PC9210 PC9214 PC9216 PC9217 PC9300 PC9301 PC9306 PC9308 PC9310-PC9316 PC9500-PC9535 PC9600-PC9608 VC3500 VC5700-VC5702 = CAP NON-POL_BGM
C423 C4108 C4109 C4728 C5003-C5022 C5305 C5827-C5830 C6300 C6301 C6303-C6305 C7619 C7621-C7626 EC9701-EC9704 PC8000-PC8004 PC8207 PC8208 PC8216 PC8226-PC8228 PC8500-PC8509 PC8615 PC8620 PC8636 PC8637 PC8639 PC8641 PC8642 PC8700-PC8708 PC8710-PC8719 PC8721-PC8725 PC8728 PC8809-PC8811 PC8815 PC8902-PC8905 PC8909 PC8912 PC8916-PC8919 PC8922 PC8925 PC9000 PC9005-PC9008 PC9016 PC9020-PC9023 PC9026 PC9033 PC9201-PC9204 PC9206 PC9211-PC9213 PC9218-PC9224 PC9302-PC9305 PC9309 = CAP_NON-POL_BGM
C4724 C4725 C5023-C5025 = Varistor_BGM
C5207 C5208 C5705 C5713 = V-PORT_0
C5706 = CAP POL_BGM
CN3400 = GS12401-1011_2
CN3500 = CON40A_2
CN3600 = 53398-0410_4
CN3601 = 2SJ-S351-001_0
CN4000 = HEADER RJ-45 FOX LED_1
CN4100 CN4300 = NGFF CONN_4
CN4200 = NGFF CONN_3
CN4201 = HEADER6_2
CN4400 CN7603 = 53398-0410_9
CN5000 = AF1263-A2G1T_1
CN5001 CN5201 CN7702 = HEADER 12_1
CN5400 = 53398-0410_6
CN5700 CN5701 = HEADER 4_0
CN6200 = CON40A_4
CN6300 = TYPEC_2
CN7600 = HEADER 12P_2
CN7601 = HEADER 6_4
CN7602 = CON40A_5
CN7700 = XDP_0
CN7701 = CON40A_1
D400 = BAT54C_BGM
D3300 D4201 D4700 = DIODE
D3600 D3601 D3603 D3605 = V-PORT
D3604 D4200 D7600-D7602 PD8205 PD8700 = Schottky_DIODE_BGM
D4300 D6200 = DIODE SCHOTTKY
D5000-D5003 = BAW56DW_1
D6300 PD8000 PD8001 PD8200 PD8201 PD8203 = ZENER_DIODE_BGM
D6301-D6304 = TVS_DIODE_UNI_BGM
F3400 F7600 = FUSE
F3401 F3402 F5200 = FUSE_BGM
H7900-H7906 H7908-H7914 H7916-H7928 H7931-H7933 = HOLE 1
JDIM2800 JDIM2801 = DDR3_1
L400 L3604 PL8700 PL9200 PR8000-PR8026 PR8100-PR8123 PR8125-PR8127 PR8129 PR8130 PR8203-PR8213 PR8215 PR8216 PR8219-PR8230 PR8233 PR8235-PR8238 PR8240-PR8248 PR8500-PR8509 PR8511-PR8520 PR8600-PR8605 PR8608-PR8610 PR8615 PR8616 PR8619 PR8622-PR8628 PR8700-PR8707 PR8712-PR8714 PR8716-PR8721 PR8723-PR8725 PR8800-PR8867 PR8900 PR8901 PR8903 PR8904 PR8906-PR8908 PR8910-PR8917 PR8920-PR8923 PR8925-PR8929 PR9000-PR9004 PR9007 PR9008 PR9010-PR9019 PR9022 PR9023 PR9025-PR9029 PR9200-PR9211 PR9214-PR9217 PR9300-PR9314 PR9500-PR9515 PR9600-PR9618 R400-R405 R411 R412 R414-R428 R430-R433 R436 R437 R439 R441-R447 R449-R458 R461-R474 R476-R479 R483-R497 R500 R501 R504-R522 R526 R528 R529 R531-R536 R539-R552 R554-R561 R563 R564 R566-R572 R574-R577 R580 R583 R584 R586-R591 R593-R595 R597-R599 R601-R623 R625-R630 R632-R635 R637-R649 R651-R657 R659 R660 R2800-R2842 R3300-R3307 R3309-R3312 R3400 R3402 R3404 R3405 R3408-R3425 R3428 R3500-R3513 R3600-R3602 R3606-R3624 R3627 R4000-R4008 R4012-R4018 R4101 R4103-R4111 R4113-R4120 R4122 R4123 R4136-R4147 R4200 R4202 R4203 R4209 R4210 R4212-R4215 R4222 R4223 R4225 R4235 R4240 R4242 R4245-R4253 R4300-R4310 R4700 R4702 R4704-R4757 R4760-R4774 R5000-R5015 R5100-R5112 R5205-R5207 R5300-R5305 R5400-R5408 R5600-R5614 R5700-R5703 R5800-R5811 R6100-R6120 R6211-R6215 R6300-R6303 R6315-R6318 R6320 R6323-R6332 R7500-R7510 R7600 R7610 R7611 R7613 R7615-R7619 R7621-R7630 R7633-R7641 R7700-R7714 R7716-R7720 R7722-R7738 R9647-R9649 = RES_BGM
L401 L5200 L5700 L5701 L7600 = BW
L402 L3400-L3402 L3600-L3603 L3605 L4000 L4700 PL8202 PL8600 PL8601 PL8701 PL8702 PL8902 PL8903 PL9000 PL9001 PL9201 PL9300 = INDUCTOR_BGM
L4200 = BW_BGM
PC8214 PC8225 PC8607 PC8616 PC8628 PC8635 PC8709 PC8720 PC8906 PC8910 PC8920 PC8923 PC8927 PC8928 PC9001 PC9009 PC9010 PC9035 PC9036 PC9307 = CAP_POL_BGM
PCN8000 = Header_8P_BGM_3
PCN8500 = 53398-0410_0
PD8100 = BAT54A_BGM
PD8101 = ZENER1 DIODE
PD8202 PD8204 PD8206 = DIODE_BGM
PD8207 = BAT54W_BGM_0
PD8500 PD8501 = BAV99W_BGM
PL8000 PL8001 PL8500 PL8501 PR8201 PR8202 PR8217 PR8218 PR8606 PR8617 PR8708-PR8711 PR8715 PR8722 PR8902 PR8905 PR8918 PR8919 PR9005 PR9006 PR9020 PR9021 = SHORTPAD_BGM
PL8200 PL8201 PL8900 PL8901 PR8611 PR8630 RR9700 = BEAD_BGM
PQ8000 PQ8001 PQ8006 PQ8007 PQ8200 = MOS-P_8P_BGM
PQ8002 PQ8003 PQ8008 PQ8009 PQ8201 Q407 Q408 Q5002 = MOS-P_3P_BGM
PQ8004 PQ8206 PQ8502 PQ8503 PQ8702 Q403 Q406 Q3400 Q3401 Q4101 Q4200 Q4300 Q4701 Q5000 Q5001 Q5003 Q5005 Q5300 Q5301 Q6100 Q6301 Q7500A Q7500B Q7502 Q7702 = MOS-N_3P_ESD_BGM
PQ8005 PQ8100 PQ8703 PQ9601 PQ9603 PQ9605 Q401 Q402 Q4000 Q4102 Q4109 Q4201 Q4202 Q4700 Q5004 Q5100 Q5400 Q5402 Q5800 Q7501 Q7700 Q7701 = MOS-N_Dual_6P_ESD_BGM
PQ8010 PQ8011 PQ8500 PQ8505 PQ8506 = PNP_BGM
PQ8012 PQ8013 PQ8202 = PNP_Dual_6P_BGM_2
PQ8203 PQ8204 PQ8701 = MOS-N_8P_SCH_BGM
PQ8501 Q404 Q3600 Q4001 Q4103 Q4105 = NPN_BGM
PQ8700 = MOS-N_8P_BGM
PQ8900 PQ8901 = MOS-N-Dual_10P_BGM
PQ9000 = MOS-N-Dual_9P_BGM
PQ9001 = SI9410_3
PQ9002 = SI9410_1
PQ9600 PQ9602 PQ9604 = MOS-N_3P_BGM
PR8200 PR8214 = R_Current_SEN_BGM
PR8909 PR8924 PR9009 PR9024 = Thermistor_BGM
PR9212 PR9213 = SHORTPAD_V01_BGM
PU8100 = AS393MTR-G1_BGM
PU8102 = Logic_Buffer W/OG_BGM
PU8200 = MAX8731EEI_12
PU8201 = G753T11U_BGM
PU8600 = SY8286BRAC_BGM
PU8601 = NB685GQ_BGM_6
PU8700 = RT8231BGQW_BGM
PU8701 = RT8097ALGE_6P_BGM
PU8800 = MP2949AGQKT-0070-Z_BGM_2
PU8900 PU8901 PU9000 PU9001 = MP8693_12P_BGM
PU9200 = AOZ2260QI-18_BGM
PU9201 = AOZ1335DI_BGM
PU9202 = MC74VHC1G08DFT2G_5P_BGM
PU9300 = NB681AGD-Z_BGM
PU9500-PU9502 = G923_0
PU9600-PU9602 = 74AHCT1G08SE-7_5P_BGM
Q4104 Q4110 = 2N7002
Q5401 = NPN_0
Q7600-Q7602 = 2N7002DW
R429 R6319 R6322 R6832 = R
R585 = 4P2R-0404_2
R5016 = RP-8
TP400-TP402 TP404 TP406 TP410 TP417 TP421-TP428 TP4000-TP4002 TP4100-TP4102 TP4200 TP4700-TP4704 TP4706 TP4707 TP4710 TP5100 TP5300 TP5600-TP5603 TP5800 TP5801 TP6100-TP6105 TP7606-TP7609 = PAD_2
TP418 TP2800-TP2803 = PAD_3
TP4300 TP7700 TP8200-TP8202 = TP_BGM
U400 = CPU_CFL_U_43E_1528P_BGM
U401 = Logic_AND_BGM
U402 = 7SH08_1
U3400 = IMISM530_0
U3500 = G5250Q1T73U_BGM
U3501 = PS8338B_3
U3600 = PS8339A_1
U4000 = RTL8111G_0
U4001 = NS680016_2
U4100 U7601 = NCT3522U_BGM_0
U4201 U5701 U5801 = BD82047FVJ-GE2_BGM_0
U4202 = NL17SZ08DFT2G_5P_BGM
U4700 = BU4S66_0
U4701 = NPCX797HA0BX_144P_BGM
U5100 = SLD9630_1
U5300 = TPA0132_0
U5301 = HP2DCTR_BGM
U5400 = LM86
U5401 = LM86_0
U5600 = SST25LF080A_0
U5700 U5702 U6300 U6301 U6303 = G995_2
U5800 = IC-PS8122PinCTL_1
U6100 = CCG5_1PORT
U6302 = NX5P3290AUK_16P_BGM
U7500 = SLG4E41618VTR_8P_BGM
U7600 = BH28PQ10LN-A1-0-TR_28P_BGM
Y400 Y4000 = CRYSTAL_4P_BGM
Y401 = CRYSTAL_2P_BGM

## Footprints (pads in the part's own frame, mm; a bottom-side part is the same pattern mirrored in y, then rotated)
2D-BARCODE-8X8-S
  round 0.991 smd: 1(7,-4)
4P2R-0404
  rect 0.33x0.762 smd: 1(-0.325,-0.5) 2(-0.325,0.5) 3(0.325,-0.5) 4(0.325,0.5)
10P8R
  rect 0.305x1.092 smd: 1(-1.27,-0.85) 2(-0.635,-0.85) 3(0,-0.85) 4(0.635,-0.85) 5(1.27,-0.85) 6(1.27,0.85) 7(0.635,0.85) 8(0,0.85) 9(-0.635,0.85) 10(-1.27,0.85)
50150-03001-001-30P-LDH
  rect 0.254x1.194 smd: 1(-3.5,-2.1) 2(-3,-2.1) 3(-2.5,-2.1) 4(-2,-2.1) 5(-1.5,-2.1) 6(-1,-2.1) 7(-0.5,-2.1) 8(0,-2.1) 9(0.5,-2.1) 10(1,-2.1) 11(1.5,-2.1) 12(2,-2.1) 13(2.5,-2.1) 14(3,-2.1) 15(3.5,-2.1) 16(3.5,2.1) 17(3,2.1) 18(2.5,2.1) 19(2,2.1) 20(1.5,2.1) 21(1,2.1) 22(0.5,2.1) 23(0,2.1) 24(-0.5,2.1) 25(-1,2.1) 26(-1.5,2.1) 27(-2,2.1) 28(-2.5,2.1) 29(-3,2.1) 30(-3.5,2.1)
  rect 1.499x2.007 smd: 31(-4.75,0) 32(4.75,0)
50281-0040N-001-4P-L
  rect 0.787x2.007 smd: 1(-1.875,4.05) 2(-0.625,4.05) 3(0.625,4.05) 4(1.875,4.05)
  rect 2.007x2.489 smd: 5(-4.075,0) 6(4.075,0)
50951-0084N-001-8P-SOCKET
  round 0.889 hole 0.889 unplated: (0,-2)
  round 1.092 hole 1.092 unplated: (0,2)
  rect 0.66x1.346 smd: 1(-3.905,-3.825) 2(-2.635,-3.825) 3(-1.365,-3.825) 4(-0.095,-3.825) 5(-0.095,3.825) 6(-1.365,3.825) 7(-2.635,3.825) 8(-3.905,3.825)
51483-00801-V01-8P-L
  rect 0.787x1.905 smd: 1(-4.375,4.925) 2(-3.125,4.925) 3(-1.875,4.925) 4(-0.625,4.925) 5(0.625,4.925) 6(1.875,4.925) 7(3.125,4.925) 8(4.375,4.925)
  rect 1.295x3.353 smd: 9(-7.225,0) 10(7.225,0)
51540-04201-V02-42P-L
  rect 0.305x0.838 smd: 1(-10.25,3.175) 2(-9.75,3.175) 3(-9.25,3.175) 4(-8.75,3.175) 5(-8.25,3.175) 6(-7.75,3.175) 7(-7.25,3.175) 8(-6.75,3.175) 9(-6.25,3.175) 10(-5.75,3.175) 11(-5.25,3.175) 12(-4.75,3.175) 13(-4.25,3.175) 14(-3.75,3.175) 15(-3.25,3.175) 16(-2.75,3.175) 17(-2.25,3.175) 18(-1.75,3.175) 19(-1.25,3.175) 20(-0.75,3.175) 21(-0.25,3.175) 22(0.25,3.175) 23(0.75,3.175) 24(1.25,3.175) 25(1.75,3.175) 26(2.25,3.175) 27(2.75,3.175) 28(3.25,3.175) 29(3.75,3.175) 30(4.25,3.175) 31(4.75,3.175) 32(5.25,3.175) 33(5.75,3.175) 34(6.25,3.175) 35(6.75,3.175) 36(7.25,3.175) 37(7.75,3.175) 38(8.25,3.175) 39(8.75,3.175) 40(9.25,3.175) 41(9.75,3.175) 42(10.25,3.175)
  rect 0.787x2.007 smd: 43(-11.95,0) 44(11.95,0)
51614-00801-V02-8P-L
  rect 0.305x0.787 smd: 1(-1.75,2.9) 2(-1.25,2.9) 3(-0.75,2.9) 4(-0.25,2.9) 5(0.25,2.9) 6(0.75,2.9) 7(1.25,2.9) 8(1.75,2.9)
  rect 0.406x0.787 smd: 9(-2.75,0.4) 10(2.75,0.4)
51619-01001-V05-10P-L
  rect 0.305x1.295 smd: 1(-2.25,2.8) 2(-1.75,2.8) 3(-1.25,2.8) 4(-0.75,2.8) 5(-0.25,2.8) 6(0.25,2.8) 7(0.75,2.8) 8(1.25,2.8) 9(1.75,2.8) 10(2.25,2.8)
  rect 1.803x1.397 smd: 11(-3.9,0) 12(3.9,0)
51625-01201-001-12P-L
  rect 0.305x0.838 smd: 1(-2.75,3.555) 2(-2.25,3.555) 3(-1.75,3.555) 4(-1.25,3.555) 5(-0.75,3.555) 6(-0.25,3.555) 7(0.25,3.555) 8(0.75,3.555) 9(1.25,3.555) 10(1.75,3.555) 11(2.25,3.555) 12(2.75,3.555)
  rect 0.991x1.448 smd: 13(-4.54,0) 14(4.54,0)
51693-0400T-V01-40P-L
  rect 0.305x1.295 smd: 1(-9.75,5.65) 2(-9.25,5.65) 3(-8.75,5.65) 4(-8.25,5.65) 5(-7.75,5.65) 6(-7.25,5.65) 7(-6.75,5.65) 8(-6.25,5.65) 9(-5.75,5.65) 10(-5.25,5.65) 11(-4.75,5.65) 12(-4.25,5.65) 13(-3.75,5.65) 14(-3.25,5.65) 15(-2.75,5.65) 16(-2.25,5.65) 17(-1.75,5.65) 18(-1.25,5.65) 19(-0.75,5.65) 20(-0.25,5.65) 21(0.25,5.65) 22(0.75,5.65) 23(1.25,5.65) 24(1.75,5.65) 25(2.25,5.65) 26(2.75,5.65) 27(3.25,5.65) 28(3.75,5.65) 29(4.25,5.65) 30(4.75,5.65) 31(5.25,5.65) 32(5.75,5.65) 33(6.25,5.65) 34(6.75,5.65) 35(7.25,5.65) 36(7.75,5.65) 37(8.25,5.65) 38(8.75,5.65) 39(9.25,5.65) 40(9.75,5.65)
  rect 1.803x2.21 smd: 41(-11.9,0) 42(11.9,0)
AUDIO-2SJ3095-186211F-6P
  oval 0.991x1.803 hole 0.61x1.397: 1(-4.8,7.175) 2(4.7,1.675) 3(-4.8,1.975) 4(-4.8,-0.625) 5(4.7,7.175) 6(4.7,4.425)
BAT-BBP28EC-B301Q-9H-8P-L-SMT
  round 1.499 hole 1.092: 1(-7,-0.25) 2(-5,-0.25) 3(-3,-0.25) 4(-1,-0.25) 5(1,-0.25) 6(3,-0.25) 7(5,-0.25) 8(7,-0.25)
  oval 2.007x3.81 hole 0.991x2.794: 9(-10.125,0) 10(10.125,0)
BGA16-NXP-NX5P3290A
  round 0.254 smd: A1(-0.75,-0.75) A2(-0.75,-0.25) A3(-0.75,0.25) A4(-0.75,0.75) B1(-0.25,-0.75) B2(-0.25,-0.25) B3(-0.25,0.25) B4(-0.25,0.75) C1(0.25,-0.75) C2(0.25,-0.25) C3(0.25,0.25) C4(0.25,0.75) D1(0.75,-0.75) D2(0.75,-0.25) D3(0.75,0.25) D4(0.75,0.75)
BGA144-NUVOTON-NPCX797H
  round 0.356 smd: A1(-3.575,-3.575) A2(-3.575,-2.925) A3(-3.575,-2.275) A4(-3.575,-1.625) A5(-3.575,-0.975) A6(-3.575,-0.325) A7(-3.575,0.325) A8(-3.575,0.975) A9(-3.575,1.625) A10(-3.575,2.275) A11(-3.575,2.925) A12(-3.575,3.575) B1(-2.925,-3.575) B2(-2.925,-2.925) B3(-2.925,-2.275) B4(-2.925,-1.625) B5(-2.925,-0.975) B6(-2.925,-0.325) B7(-2.925,0.325) B8(-2.925,0.975) B9(-2.925,1.625) B10(-2.925,2.275) B11(-2.925,2.925) B12(-2.925,3.575) C1(-2.275,-3.575) C2(-2.275,-2.925) C3(-2.275,-2.275) C4(-2.275,-1.625) C5(-2.275,-0.975) C6(-2.275,-0.325) C7(-2.275,0.325) C8(-2.275,0.975) C9(-2.275,1.625) C10(-2.275,2.275) C11(-2.275,2.925) C12(-2.275,3.575) D1(-1.625,-3.575) D2(-1.625,-2.925) D3(-1.625,-2.275) D4(-1.625,-1.625) D5(-1.625,-0.975) D6(-1.625,-0.325) D7(-1.625,0.325) D8(-1.625,0.975) D9(-1.625,1.625) D10(-1.625,2.275) D11(-1.625,2.925) D12(-1.625,3.575) E1(-0.975,-3.575) E2(-0.975,-2.925) E3(-0.975,-2.275) E4(-0.975,-1.625) E5(-0.975,-0.975) E6(-0.975,-0.325) E7(-0.975,0.325) E8(-0.975,0.975) E9(-0.975,1.625) E10(-0.975,2.275) E11(-0.975,2.925) E12(-0.975,3.575) F1(-0.325,-3.575) F2(-0.325,-2.925) F3(-0.325,-2.275) F4(-0.325,-1.625) F5(-0.325,-0.975) F6(-0.325,-0.325) F7(-0.325,0.325) F8(-0.325,0.975) F9(-0.325,1.625) F10(-0.325,2.275) F11(-0.325,2.925) F12(-0.325,3.575) G1(0.325,-3.575) G2(0.325,-2.925) G3(0.325,-2.275) G4(0.325,-1.625) G5(0.325,-0.975) G6(0.325,-0.325) G7(0.325,0.325) G8(0.325,0.975) G9(0.325,1.625) G10(0.325,2.275) G11(0.325,2.925) G12(0.325,3.575) H1(0.975,-3.575) H2(0.975,-2.925) H3(0.975,-2.275) H4(0.975,-1.625) H5(0.975,-0.975) H6(0.975,-0.325) H7(0.975,0.325) H8(0.975,0.975) H9(0.975,1.625) H10(0.975,2.275) H11(0.975,2.925) H12(0.975,3.575) J1(1.625,-3.575) J2(1.625,-2.925) J3(1.625,-2.275) J4(1.625,-1.625) J5(1.625,-0.975) J6(1.625,-0.325) J7(1.625,0.325) J8(1.625,0.975) J9(1.625,1.625) J10(1.625,2.275) J11(1.625,2.925) J12(1.625,3.575) K1(2.275,-3.575) K2(2.275,-2.925) K3(2.275,-2.275) K4(2.275,-1.625) K5(2.275,-0.975) K6(2.275,-0.325) K7(2.275,0.325) K8(2.275,0.975) K9(2.275,1.625) K10(2.275,2.275) K11(2.275,2.925) K12(2.275,3.575) L1(2.925,-3.575) L2(2.925,-2.925) L3(2.925,-2.275) L4(2.925,-1.625) L5(2.925,-0.975) L6(2.925,-0.325) L7(2.925,0.325) L8(2.925,0.975) L9(2.925,1.625) L10(2.925,2.275) L11(2.925,2.925) L12(2.925,3.575) M1(3.575,-3.575) M2(3.575,-2.925) M3(3.575,-2.275) M4(3.575,-1.625) M5(3.575,-0.975) M6(3.575,-0.325) M7(3.575,0.325) M8(3.575,0.975) M9(3.575,1.625) M10(3.575,2.275) M11(3.575,2.925) M12(3.575,3.575)
BGA1528-INTEL-WHL-U
  round 0.356 smd: A3(-22.315,-10.396) A36(-22.315,10.855) B2(-21.855,-10.855) B37(-21.855,11.315) C1(-21.396,-11.315) CP1(21.855,-11.315) CP37(21.855,11.315) CR2(22.315,-10.855) CR36(22.315,10.855)
  round 0.33 smd: A4(-22.315,-9.746) A35(-22.315,10.205) B3(-21.687,-10.227) B36(-21.687,10.687) C2(-21.227,-10.687) C37(-21.205,11.315) CN1(21.205,-11.315) CN37(21.205,11.315) CP2(21.687,-10.687) CP36(21.687,10.687) CR3(22.315,-10.205) CR35(22.315,10.205) D1(-20.746,-11.315)
  round 0.305 smd: A5(-22.292,-9.096) A6(-22.315,-8.232) A32(-22.315,8.228) A34(-22.315,9.555) AA4(-10.421,-9.365) AA9(-10.624,-6.21) AA24(-10.481,3.679) AA26(-10.481,4.606) AA34(-10.719,9.365) AB3(-9.763,-10.334) AB4(-9.763,-9.325) AB5(-10.162,-8.617) AB6(-10.162,-7.967) AB7(-10.162,-7.317) AB8(-10.162,-6.668) AB9(-9.7,-6.21) AB10(-10.162,-5.753) AB25(-10.025,4.142) AB27(-10.025,5.069) AB28(-10.025,5.719) AB29(-10.025,6.369) AB30(-10.025,7.019) AB31(-10.025,7.669) AB32(-10.025,8.32) AB33(-10.068,9.04) AB34(-10.068,9.69) AC4(-9.106,-9.365) AC5(-9.238,-8.617) AC6(-9.238,-7.967) AC7(-9.238,-7.317) AC8(-9.238,-6.668) AC10(-9.238,-5.753) AC24(-9.57,3.679) AC25(-9.114,4.142) AC26(-9.57,4.606) AC27(-9.114,5.069) AC28(-9.114,5.719) AC29(-9.114,6.369) AC30(-9.114,7.019) AC31(-9.114,7.669) AC32(-9.114,8.32) AC34(-9.417,9.365) AD4(-8.543,-9.69) AD9(-8.776,-6.21) AD24(-8.658,3.679) AD26(-8.658,4.606) AD33(-8.809,9.04) AD35(-8.809,10.245) AE4(-7.98,-9.365) AE5(-8.314,-8.617) AE6(-8.314,-7.967) AE7(-8.314,-7.317) AE8(-8.314,-6.668) AE9(-7.852,-6.21) AE10(-8.314,-5.753) AE24(-7.747,3.679) AE25(-8.203,4.142) AE26(-7.747,4.606) AE27(-8.203,5.069) AE28(-8.203,5.719) AE29(-8.203,6.369) AE30(-8.203,7.019) AE31(-8.203,7.669) AE32(-8.203,8.32) AE34(-8.202,9.365) AF3(-7.322,-10.334) AF4(-7.322,-9.325) AF5(-7.39,-8.617) AF6(-7.39,-7.967) AF7(-7.39,-7.317) AF8(-7.39,-6.668) AF10(-7.39,-5.753) AF25(-7.291,4.142) AF27(-7.291,5.069) AF28(-7.291,5.719) AF29(-7.291,6.369) AF30(-7.291,7.019) AF31(-7.291,7.669) AF32(-7.291,8.32) AF33(-7.551,9.04) AF34(-7.551,9.69) AG4(-6.665,-9.365) AG5(-6.467,-8.617) AG6(-6.467,-7.967) AG7(-6.467,-7.317) AG8(-6.467,-6.668) AG9(-6.929,-6.21) AG10(-6.467,-5.753) AG24(-6.835,3.679) AG26(-6.835,4.606) AG34(-6.9,9.365) AH4(-6.102,-9.69) AH9(-6.005,-6.21) AH24(-5.924,3.679) AH25(-6.38,4.142) AH26(-5.924,4.606) AH27(-6.38,5.069) AH28(-6.38,5.719) AH29(-6.38,6.369) AH30(-6.38,7.019) AH31(-6.38,7.669) AH32(-6.38,8.32) AH33(-6.293,9.04) AH35(-6.293,10.245) AJ4(-5.539,-9.365) AJ5(-5.543,-8.617) AJ6(-5.543,-7.967) AJ7(-5.543,-7.317) AJ8(-5.543,-6.668) AJ10(-5.543,-5.753) AJ25(-5.468,4.142) AJ27(-5.468,5.069) AJ28(-5.468,5.719) AJ29(-5.468,6.369) AJ30(-5.468,7.019) AJ31(-5.468,7.669) AJ32(-5.468,8.32) AJ34(-5.685,9.365) AK3(-4.882,-10.334) AK4(-4.882,-9.325) AK9(-5.081,-6.21) AK24(-5.013,3.679) AK26(-5.013,4.606) AK33(-5.034,9.04) AK34(-5.034,9.69) AL4(-4.224,-9.365) AL5(-4.619,-8.617) AL6(-4.619,-7.967) AL7(-4.619,-7.317) AL8(-4.619,-6.668) AL9(-4.157,-6.21) AL10(-4.619,-5.753) AL24(-4.101,3.679) AL25(-4.557,4.142) AL26(-4.101,4.606) AL27(-4.557,5.069) AL28(-4.557,5.719) AL29(-4.557,6.369) AL30(-4.557,7.019) AL31(-4.557,7.669) AL32(-4.557,8.32) AL34(-4.383,9.365) AM4(-3.661,-9.69) AM5(-3.695,-8.617) AM6(-3.695,-7.967) AM7(-3.695,-7.317) AM8(-3.695,-6.668) AM10(-3.695,-5.753) AM25(-3.646,4.142) AM27(-3.646,5.069) AM28(-3.646,5.719) AM29(-3.646,6.369) AM30(-3.646,7.019) AM31(-3.646,7.669) AM32(-3.646,8.32) AM33(-3.775,9.04) AM35(-3.775,10.245) AN4(-3.098,-9.365) AN5(-2.771,-8.617) AN6(-2.771,-7.967) AN7(-2.771,-7.317) AN8(-2.771,-6.668) AN9(-3.233,-6.21) AN10(-2.771,-5.753) AN24(-3.19,3.679) AN25(-2.734,4.142) AN26(-3.19,4.606) AN27(-2.734,5.069) AN28(-2.734,5.719) AN29(-2.734,6.369) AN30(-2.734,7.019) AN31(-2.734,7.669) AN32(-2.734,8.32) AN34(-3.168,9.365) AP3(-2.441,-10.334) AP4(-2.441,-9.325) AP9(-2.31,-6.21) AP24(-2.278,3.679) AP26(-2.278,4.606) AP33(-2.517,9.04) AP34(-2.517,9.69) AR4(-1.783,-9.365) AR5(-1.848,-8.617) AR6(-1.848,-7.967) AR7(-1.848,-7.317) AR8(-1.848,-6.668) AR10(-1.848,-5.753) AR25(-1.823,4.142) AR27(-1.823,5.069) AR28(-1.823,5.719) AR29(-1.823,6.369) AR30(-1.823,7.019) AR31(-1.823,7.669) AR32(-1.823,8.32) AR34(-1.866,9.365) AT4(-1.22,-9.69) AT9(-1.386,-6.21) AT24(-1.367,3.679) AT26(-1.367,4.606) AT33(-1.259,9.04) AT35(-1.259,10.245) AU4(-0.657,-9.365) AU5(-0.924,-8.617) AU6(-0.924,-7.967) AU7(-0.924,-7.317) AU8(-0.924,-6.668) AU9(-0.462,-6.21) AU10(-0.924,-5.753) AU24(-0.456,3.679) AU25(-0.911,4.142) AU26(-0.456,4.606) AU27(-0.911,5.069) AU28(-0.911,5.719) AU29(-0.911,6.369) AU30(-0.911,7.019) AU31(-0.911,7.669) AU32(-0.911,8.32) AU34(-0.65,9.365) AV3(0,-10.334) AV4(0,-9.325) AV5(0,-8.617) AV6(0,-7.967) AV7(0,-7.317) AV8(0,-6.668) AV10(0,-5.753) AV25(0,4.142) AV27(0,5.069) AV28(0,5.719) AV29(0,6.369) AV30(0,7.019) AV31(0,7.669) AV32(0,8.32) AV33(0,9.04) AV34(0,9.69) AW4(0.657,-9.365) AW5(0.924,-8.617) AW6(0.924,-7.967) AW7(0.924,-7.317) AW8(0.924,-6.668) AW9(0.462,-6.21) AW10(0.924,-5.753) AW24(0.456,3.679) AW25(0.911,4.142) AW26(0.456,4.606) AW27(0.911,5.069) AW28(0.911,5.719) AW29(0.911,6.369) AW30(0.911,7.019) AW31(0.911,7.669) AW32(0.911,8.32) AW34(0.65,9.365) AY4(1.22,-9.69) AY9(1.386,-6.21) AY24(1.367,3.679) AY26(1.367,4.606) AY33(1.259,9.04) AY35(1.259,10.245) B4(-21.707,-9.515) B5(-21.684,-8.866) B33(-22.004,8.901) B34(-21.582,9.396) B35(-21.687,10.037) BA4(1.783,-9.365) BA5(1.848,-8.617) BA6(1.848,-7.967) BA7(1.848,-7.317) BA8(1.848,-6.668) BA10(1.848,-5.753) BA25(1.823,4.142) BA27(1.823,5.069) BA28(1.823,5.719) BA29(1.823,6.369) BA30(1.823,7.019) BA31(1.823,7.669) BA32(1.823,8.32) BA34(1.866,9.365) BB3(2.441,-10.334) BB4(2.441,-9.325) BB9(2.31,-6.21) BB24(2.278,3.679) BB26(2.278,4.606) BB33(2.517,9.04) BB34(2.517,9.69) BC4(3.098,-9.365) BC5(2.771,-8.617) BC6(2.771,-7.967) BC7(2.771,-7.317) BC8(2.771,-6.668) BC9(3.233,-6.21) BC10(2.771,-5.753) BC24(3.19,3.679) BC25(2.734,4.142) BC26(3.19,4.606) BC27(2.734,5.069) BC28(2.734,5.719) BC29(2.734,6.369) BC30(2.734,7.019) BC31(2.734,7.669) BC32(2.734,8.32) BC34(3.168,9.365) BD4(3.661,-9.69) BD5(3.695,-8.617) BD6(3.695,-7.967) BD7(3.695,-7.317) BD8(3.695,-6.668) BD10(3.695,-5.753) BD25(3.646,4.142) BD27(3.646,5.069) BD28(3.646,5.719) BD29(3.646,6.369) BD30(3.646,7.019) BD31(3.646,7.669) BD32(3.646,8.32) BD33(3.775,9.04) BD35(3.775,10.245) BE4(4.224,-9.365) BE5(4.619,-8.617) BE6(4.619,-7.967) BE7(4.619,-7.317) BE8(4.619,-6.668) BE9(4.157,-6.21) BE10(4.619,-5.753) BE24(4.101,3.679) BE25(4.557,4.142) BE26(4.101,4.606) BE27(4.557,5.069) BE28(4.557,5.719) BE29(4.557,6.369) BE30(4.557,7.019) BE31(4.557,7.669) BE32(4.557,8.32) BE34(4.383,9.365) BF3(4.882,-10.334) BF4(4.882,-9.325) BF9(5.081,-6.21) BF24(5.013,3.679) BF26(5.013,4.606) BF33(5.034,9.04) BF34(5.034,9.69) BG4(5.539,-9.365) BG5(5.543,-8.617) BG6(5.543,-7.967) BG7(5.543,-7.317) BG8(5.543,-6.668) BG10(5.543,-5.753) BG25(5.468,4.142) BG27(5.468,5.069) BG28(5.468,5.719) BG29(5.468,6.369) BG30(5.468,7.019) BG31(5.468,7.669) BG32(5.468,8.32) BG34(5.685,9.365) BH4(6.102,-9.69) BH9(6.005,-6.21) BH24(5.924,3.679) BH25(6.38,4.142) BH26(5.924,4.606) BH27(6.38,5.069) BH28(6.38,5.719) BH29(6.38,6.369) BH30(6.38,7.019) BH31(6.38,7.669) BH32(6.38,8.32) BH33(6.293,9.04) BH35(6.293,10.245) BJ4(6.665,-9.365) BJ5(6.467,-8.617) BJ6(6.467,-7.967) BJ7(6.467,-7.317) BJ8(6.467,-6.668) BJ9(6.929,-6.21) BJ10(6.467,-5.753) BJ24(6.835,3.679) BJ26(6.835,4.606) BJ34(6.9,9.365) BK3(7.322,-10.334) BK4(7.322,-9.325) BK5(7.39,-8.617) BK6(7.39,-7.967) BK7(7.39,-7.317) BK8(7.39,-6.668) BK10(7.39,-5.753) BK25(7.291,4.142) BK27(7.291,5.069) BK28(7.291,5.719) BK29(7.291,6.369) BK30(7.291,7.019) BK31(7.291,7.669) BK32(7.291,8.32) BK33(7.551,9.04) BK34(7.551,9.69) BL4(7.98,-9.365) BL5(8.314,-8.617) BL6(8.314,-7.967) BL7(8.314,-7.317) BL8(8.314,-6.668) BL9(7.852,-6.21) BL10(8.314,-5.753) BL24(7.747,3.679) BL25(8.203,4.142) BL26(7.747,4.606) BL27(8.203,5.069) BL28(8.203,5.719) BL29(8.203,6.369) BL30(8.203,7.019) BL31(8.203,7.669) BL32(8.203,8.32) BL34(8.202,9.365) BM4(8.543,-9.69) BM9(8.776,-6.21) BM24(8.658,3.679) BM26(8.658,4.606) BM33(8.809,9.04) BM35(8.809,10.245) BN4(9.106,-9.365) BN5(9.238,-8.617) BN6(9.238,-7.967) BN7(9.238,-7.317) BN8(9.238,-6.668) BN10(9.238,-5.753) BN25(9.114,4.142) BN27(9.114,5.069) BN28(9.114,5.719) BN29(9.114,6.369) BN30(9.114,7.019) BN31(9.114,7.669) BN32(9.114,8.32) BN34(9.417,9.365) BP3(9.763,-10.334) BP4(9.763,-9.325) BP5(10.162,-8.617) BP6(10.162,-7.967) BP7(10.162,-7.317) BP8(10.162,-6.668) BP9(10.162,-6.018) BP11(9.786,-5.093) BP12(9.786,-4.253) BP14(9.786,-3.413) BP15(9.786,-2.574) BP16(9.786,-1.734) BP18(9.786,-0.894) BP19(9.786,-0.054) BP20(9.786,0.786) BP22(9.786,1.626) BP23(9.786,2.465) BP24(9.786,3.305) BP25(9.786,4.145) BP27(10.025,5.069) BP28(10.025,5.719) BP29(10.025,6.369) BP30(10.025,7.019) BP31(10.025,7.669) BP32(10.025,8.32) BP33(10.068,9.04) BP34(10.068,9.69) BR4(10.421,-9.365) BR11(10.436,-5.093) BR12(10.436,-4.253) BR14(10.436,-3.413) BR15(10.436,-2.574) BR16(10.436,-1.734) BR18(10.436,-0.894) BR19(10.436,-0.054) BR20(10.436,0.786) BR22(10.436,1.626) BR23(10.436,2.465) BR24(10.436,3.305) BR25(10.436,4.145) BR34(10.719,9.365) BT4(10.984,-9.69) BT5(11.086,-8.617) BT6(11.086,-7.967) BT7(11.086,-7.317) BT8(11.086,-6.668) BT9(11.086,-6.018) BT11(11.086,-5.093) BT12(11.086,-4.253) BT14(11.086,-3.413) BT15(11.086,-2.574) BT16(11.086,-1.734) BT18(11.086,-0.894) BT19(11.086,-0.054) BT20(11.086,0.786) BT22(11.086,1.626) BT23(11.086,2.465) BT24(11.086,3.305) BT25(11.086,4.145) BT27(10.937,5.069) BT28(10.937,5.719) BT29(10.937,6.369) BT30(10.937,7.019) BT31(10.937,7.669) BT32(10.937,8.32) BT33(11.327,9.04) BT35(11.327,10.245) BU4(11.547,-9.365) BU5(12.009,-8.617) BU6(12.009,-7.967) BU7(12.009,-7.317) BU8(12.009,-6.668) BU9(12.009,-6.018) BU11(11.736,-5.093) BU12(11.736,-4.253) BU14(11.736,-3.413) BU15(11.736,-2.574) BU16(11.736,-1.734) BU18(11.736,-0.894) BU19(11.736,-0.054) BU20(11.736,0.786) BU22(11.736,1.626) BU23(11.736,2.465) BU24(11.736,3.305) BU25(11.736,4.145) BU27(11.848,5.069) BU28(11.848,5.719) BU29(11.848,6.369) BU30(11.848,7.019) BU31(11.848,7.669) BU32(11.848,8.32) BU34(11.934,9.365) BV3(12.204,-10.334) BV4(12.204,-9.325) BV11(12.386,-5.093) BV12(12.386,-4.253) BV14(12.386,-3.413) BV15(12.386,-2.574) BV16(12.386,-1.734) BV18(12.386,-0.894) BV19(12.386,-0.054) BV20(12.386,0.786) BV22(12.386,1.626) BV23(12.386,2.465) BV24(12.386,3.305) BV25(12.386,4.145) BV27(12.76,5.069) BV28(12.76,5.719) BV29(12.76,6.369) BV30(12.76,7.019) BV31(12.76,7.669) BV32(12.76,8.32) BV33(12.585,9.04) BV34(12.585,9.69) BW4(12.861,-9.365) BW5(12.933,-8.617) BW6(12.933,-7.967) BW7(12.933,-7.317) BW8(12.933,-6.668) BW9(12.933,-6.018) BW11(13.036,-5.093) BW12(13.036,-4.253) BW14(13.036,-3.413) BW15(13.036,-2.574) BW16(13.036,-1.734) BW18(13.036,-0.894) BW19(13.036,-0.054) BW20(13.036,0.786) BW22(13.036,1.626) BW23(13.036,2.465) BW24(13.036,3.305) BW25(13.036,4.145) BW34(13.236,9.365) BY4(13.424,-9.69) BY5(13.857,-8.617) BY6(13.857,-7.967) BY7(13.857,-7.317) BY8(13.857,-6.668) BY9(13.857,-6.018) BY11(13.686,-5.093) BY12(13.686,-4.253) BY14(13.686,-3.413) BY15(13.686,-2.574) BY16(13.686,-1.734) BY18(13.686,-0.894) BY19(13.686,-0.054) BY20(13.686,0.786) BY22(13.686,1.626) BY23(13.686,2.465) BY24(13.686,3.305) BY25(13.686,4.145) BY27(13.671,5.069) BY28(13.671,5.719) BY29(13.671,6.369) BY30(13.671,7.019) BY31(13.671,7.669) BY32(13.671,8.32) BY33(13.844,9.04) BY35(13.844,10.245) C3(-21.059,-10.059) C4(-21.132,-9.213) C9(-21.245,-6.305) C21(-21.245,1.275) C25(-21.245,3.792) C29(-21.245,6.309) C33(-21.245,8.826) C34(-20.932,9.396) C35(-21.037,10.037) C36(-21.037,10.687) CA4(13.988,-9.365) CA11(14.336,-5.093) CA12(14.336,-4.253) CA14(14.336,-3.413) CA15(14.336,-2.574) CA16(14.336,-1.734) CA18(14.336,-0.894) CA19(14.336,-0.054) CA20(14.336,0.786) CA22(14.336,1.626) CA23(14.336,2.465) CA24(14.336,3.305) CA25(14.336,4.145) CA27(14.582,5.069) CA28(14.582,5.719) CA29(14.582,6.369) CA30(14.582,7.019) CA31(14.582,7.669) CA32(14.582,8.32) CA34(14.451,9.365) CB3(14.645,-10.334) CB4(14.645,-9.325) CB5(14.781,-8.617) CB6(14.781,-7.967) CB7(14.781,-7.317) CB8(14.781,-6.668) CB9(14.781,-6.018) CB11(14.985,-5.093) CB12(14.985,-4.253) CB14(14.985,-3.413) CB15(14.985,-2.574) CB16(14.985,-1.734) CB18(14.985,-0.894) CB19(14.985,-0.054) CB20(14.985,0.786) CB22(14.985,1.626) CB23(14.985,2.465) CB24(14.985,3.305) CB25(14.985,4.145) CB33(15.102,9.04) CB34(15.102,9.69) CC4(15.302,-9.365) CC5(15.705,-8.617) CC6(15.705,-7.967) CC7(15.705,-7.317) CC8(15.705,-6.668) CC9(15.705,-6.018) CC11(15.635,-5.093) CC12(15.635,-4.253) CC14(15.635,-3.413) CC15(15.635,-2.574) CC16(15.635,-1.734) CC18(15.635,-0.894) CC19(15.635,-0.054) CC20(15.635,0.786) CC22(15.635,1.626) CC23(15.635,2.465) CC24(15.635,3.305) CC25(15.635,4.145) CC27(15.494,5.069) CC28(15.494,5.719) CC29(15.494,6.369) CC30(15.494,7.019) CC31(15.494,7.669) CC32(15.494,8.32) CC34(15.753,9.365) CD4(15.865,-9.69) CD11(16.285,-5.093) CD12(16.285,-4.253) CD14(16.285,-3.413) CD15(16.285,-2.574) CD16(16.285,-1.734) CD18(16.285,-0.894) CD19(16.285,-0.054) CD20(16.285,0.786) CD22(16.285,1.626) CD23(16.285,2.465) CD24(16.285,3.305) CD25(16.285,4.145) CE4(16.428,-9.365) CE5(16.628,-8.617) CE6(16.628,-7.967) CE7(16.628,-7.317) CE8(16.628,-6.668) CE9(16.628,-6.018) CE27(16.405,5.069) CE28(16.405,5.719) CE29(16.405,6.369) CE30(16.405,7.019) CE31(16.405,7.669) CE32(16.405,8.32) CE33(16.36,9.04) CE35(16.36,10.245) CF3(17.086,-10.334) CF4(17.086,-9.325) CF11(17.115,-5.37) CF12(17.115,-4.368) CF14(17.115,-3.33) CF15(17.115,-2.292) CF17(17.115,-1.254) CF19(17.115,-0.216) CF20(17.115,0.822) CF22(17.115,1.86) CF23(17.115,2.898) CF25(17.115,3.936) CF27(17.317,5.069) CF28(17.317,5.719) CF29(17.317,6.369) CF30(17.317,7.019) CF31(17.317,7.669) CF32(17.317,8.32) CF34(16.968,9.365) CG4(17.743,-9.365) CG5(17.552,-8.617) CG6(17.552,-7.967) CG7(17.552,-7.317) CG8(17.552,-6.668) CG9(17.552,-6.018) CG11(17.765,-5.37) CG12(17.765,-4.368) CG14(17.765,-3.33) CG15(17.765,-2.292) CG17(17.765,-1.254) CG19(17.765,-0.216) CG20(17.765,0.822) CG22(17.765,1.86) CG23(17.765,2.898) CG25(17.765,3.936) CG33(17.619,9.04) CG34(17.619,9.69) CH4(18.306,-9.69) CH5(18.476,-8.617) CH6(18.476,-7.967) CH7(18.476,-7.317) CH8(18.476,-6.668) CH9(18.476,-6.018) CH11(18.415,-5.37) CH12(18.415,-4.368) CH14(18.415,-3.33) CH15(18.415,-2.292) CH17(18.415,-1.254) CH19(18.415,-0.216) CH20(18.415,0.822) CH22(18.415,1.86) CH23(18.415,2.898) CH25(18.415,3.936) CH27(18.228,5.069) CH28(18.228,5.719) CH29(18.228,6.369) CH30(18.228,7.019) CH31(18.228,7.669) CH32(18.228,8.32) CH34(18.27,9.365) CJ4(18.869,-9.365) CJ11(19.065,-5.37) CJ12(19.065,-4.368) CJ14(19.065,-3.33) CJ15(19.065,-2.292) CJ17(19.065,-1.254) CJ19(19.065,-0.216) CJ20(19.065,0.822) CJ22(19.065,1.86) CJ23(19.065,2.898) CJ25(19.065,3.936) CJ27(19.139,5.069) CJ28(19.139,5.719) CJ29(19.139,6.369) CJ30(19.139,7.019) CJ31(19.139,7.669) CJ32(19.139,8.32) CJ33(18.833,9.04) CJ35(18.878,10.245) CK1(19.561,-11.315) CK3(19.83,-9.895) CK4(19.518,-9.325) CK5(19.4,-8.617) CK6(19.4,-7.967) CK7(19.4,-7.317) CK8(19.4,-6.668) CK9(19.4,-6.018) CK11(19.715,-5.37) CK12(19.715,-4.368) CK14(19.715,-3.33) CK15(19.715,-2.292) CK17(19.715,-1.254) CK19(19.715,-0.216) CK20(19.715,0.822) CK22(19.715,1.86) CK23(19.715,2.898) CK25(19.715,3.936) CK33(19.504,9.15) CK34(19.326,9.775) CK36(19.462,10.612) CK37(19.374,11.315) CL2(20.058,-10.896) CL35(19.91,10.061) CL36(20.019,10.948) CM1(20.555,-11.315) CM3(20.383,-10.333) CM4(20.343,-9.496) CM5(20.365,-8.782) CM6(20.371,-8.132) CM7(20.69,-7.565) CM8(20.371,-6.999) CM9(20.365,-6.305) CM10(20.371,-5.61) CM11(20.69,-5.044) CM12(20.371,-4.478) CM13(20.365,-3.783) CM14(20.371,-3.088) CM15(20.69,-2.522) CM16(20.371,-1.956) CM17(20.365,-1.261) CM18(20.371,-0.566) CM19(20.69,0) CM20(20.371,0.566) CM21(20.365,1.261) CM22(20.371,1.956) CM23(20.69,2.522) CM24(20.371,3.088) CM25(20.365,3.783) CM26(20.371,4.478) CM27(20.69,5.044) CM28(20.371,5.61) CM29(20.365,6.305) CM30(20.365,6.955) CM31(20.814,7.531) CM32(20.365,8.176) CM33(20.365,8.826) CM34(20.286,9.471) CM35(20.433,10.447) CM37(20.555,11.315) CN2(20.88,-10.752) CN3(20.946,-10.007) CN4(20.978,-9.358) CN5(21.367,-8.794) CN9(21.245,-6.305) CN13(21.245,-3.783) CN17(21.245,-1.261) CN21(21.245,1.261) CN25(21.245,3.783) CN29(21.245,6.305) CN33(21.245,8.826) CN34(20.932,9.396) CN35(21.037,10.037) CN36(21.037,10.687) CP3(21.687,-10.037) CP4(21.627,-9.39) CP5(22.099,-8.942) CP33(21.968,8.871) CP34(21.582,9.396) CP35(21.687,10.037) CR4(22.315,-9.555) CR6(22.315,-8.232) CR32(22.315,8.321) CR34(22.315,9.555) D2(-20.579,-10.64) D4(-20.605,-9.594) D5(-20.365,-8.782) D6(-20.371,-8.132) D7(-20.69,-7.565) D8(-20.371,-6.999) D9(-20.505,-6.305) D21(-20.595,1.275) D22(-20.365,1.883) D23(-20.69,2.534) D24(-20.365,3.184) D25(-20.595,3.792) D26(-20.365,4.4) D27(-20.69,5.051) D28(-20.365,5.701) D30(-20.365,6.917) D31(-20.69,7.568) D32(-20.365,8.218) D34(-20.282,9.396) D35(-20.433,10.447) D37(-20.555,11.315) E1(-20.096,-11.315) E3(-20.089,-10.008) E4(-19.995,-9.365) E9(-19.862,-6.21) E23(-20.04,2.621) E27(-20.04,5.051) E29(-20.04,6.309) E31(-20.04,7.568) E33(-20.04,8.781) E35(-19.91,10.061) E36(-20.019,10.948) F2(-19.527,-11.001) F3(-19.527,-10.334) F4(-19.432,-9.69) F5(-19.4,-8.617) F6(-19.4,-7.967) F7(-19.4,-7.317) F8(-19.4,-6.668) F21(-19.715,1.149) F22(-19.715,2.058) F24(-19.715,3.184) F25(-19.715,4.093) F33(-19.504,9.15) F34(-19.326,9.775) F36(-19.462,10.612) F37(-19.374,11.315) G1(-18.844,-11.315) G4(-18.869,-9.365) G9(-18.938,-6.21) G21(-19.065,1.149) G22(-19.065,2.058) G24(-19.065,3.184) G25(-19.065,4.093) G27(-19.139,5.069) G28(-19.139,5.719) G29(-19.139,6.369) G30(-19.139,7.019) G31(-19.139,7.669) G32(-19.139,8.32) G33(-18.833,9.04) G35(-18.878,10.245) H4(-18.306,-9.69) H5(-18.476,-8.617) H6(-18.476,-7.967) H7(-18.476,-7.317) H8(-18.476,-6.668) H9(-18.014,-6.21) H21(-18.415,1.149) H22(-18.415,2.058) H24(-18.415,3.184) H25(-18.415,4.093) H27(-18.228,5.069) H28(-18.228,5.719) H29(-18.228,6.369) H30(-18.228,7.019) H31(-18.228,7.669) H32(-18.228,8.32) H34(-18.27,9.365) J4(-17.743,-9.365) J5(-17.552,-8.617) J6(-17.552,-7.967) J7(-17.552,-7.317) J8(-17.552,-6.668) J21(-17.765,1.149) J22(-17.765,2.058) J24(-17.765,3.184) J25(-17.765,4.093) J33(-17.619,9.04) J34(-17.619,9.69) K3(-17.086,-10.334) K4(-17.086,-9.325) K9(-17.09,-6.21) K11(-17.115,-5.322) K12(-17.115,-4.38) K14(-17.115,-3.438) K15(-17.115,-2.496) K17(-17.115,-1.554) K18(-17.115,-0.613) K20(-17.115,0.329) K21(-17.115,1.149) K22(-17.115,2.058) K24(-17.115,3.184) K25(-17.115,4.093) K27(-17.317,5.069) K28(-17.317,5.719) K29(-17.317,6.369) K30(-17.317,7.019) K31(-17.317,7.669) K32(-17.317,8.32) K34(-16.968,9.365) L4(-16.428,-9.365) L5(-16.628,-8.617) L6(-16.628,-7.967) L7(-16.628,-7.317) L8(-16.628,-6.668) L10(-16.628,-5.753) L25(-16.405,4.142) L27(-16.405,5.069) L28(-16.405,5.719) L29(-16.405,6.369) L30(-16.405,7.019) L31(-16.405,7.669) L32(-16.405,8.32) L33(-16.36,9.04) L35(-16.36,10.245) M4(-15.865,-9.69) M9(-16.167,-6.21) M24(-15.949,3.679) M26(-15.949,4.606) N4(-15.302,-9.365) N5(-15.705,-8.617) N6(-15.705,-7.967) N7(-15.705,-7.317) N8(-15.705,-6.668) N9(-15.243,-6.21) N10(-15.705,-5.753) N25(-15.494,4.142) N27(-15.494,5.069) N28(-15.494,5.719) N29(-15.494,6.369) N30(-15.494,7.019) N31(-15.494,7.669) N32(-15.494,8.32) N34(-15.753,9.365) P3(-14.645,-10.334) P4(-14.645,-9.325) P5(-14.781,-8.617) P6(-14.781,-7.967) P7(-14.781,-7.317) P8(-14.781,-6.668) P10(-14.781,-5.753) P24(-15.038,3.679) P26(-15.038,4.606) P33(-15.102,9.04) P34(-15.102,9.69) R4(-13.988,-9.365) R9(-14.319,-6.21) R24(-14.127,3.679) R25(-14.582,4.142) R26(-14.127,4.606) R27(-14.582,5.069) R28(-14.582,5.719) R29(-14.582,6.369) R30(-14.582,7.019) R31(-14.582,7.669) R32(-14.582,8.32) R34(-14.451,9.365) T4(-13.424,-9.69) T5(-13.857,-8.617) T6(-13.857,-7.967) T7(-13.857,-7.317) T8(-13.857,-6.668) T9(-13.395,-6.21) T10(-13.857,-5.753) T25(-13.671,4.142) T27(-13.671,5.069) T28(-13.671,5.719) T29(-13.671,6.369) T30(-13.671,7.019) T31(-13.671,7.669) T32(-13.671,8.32) T33(-13.844,9.04) T35(-13.844,10.245) U4(-12.861,-9.365) U5(-12.933,-8.617) U6(-12.933,-7.967) U7(-12.933,-7.317) U8(-12.933,-6.668) U10(-12.933,-5.753) U24(-13.215,3.679) U26(-13.215,4.606) U34(-13.236,9.365) V3(-12.204,-10.334) V4(-12.204,-9.325) V9(-12.471,-6.21) V24(-12.304,3.679) V25(-12.76,4.142) V26(-12.304,4.606) V27(-12.76,5.069) V28(-12.76,5.719) V29(-12.76,6.369) V30(-12.76,7.019) V31(-12.76,7.669) V32(-12.76,8.32) V33(-12.585,9.04) V34(-12.585,9.69) W4(-11.547,-9.365) W5(-12.009,-8.617) W6(-12.009,-7.967) W7(-12.009,-7.317) W8(-12.009,-6.668) W9(-11.548,-6.21) W10(-12.009,-5.753) W25(-11.848,4.142) W27(-11.848,5.069) W28(-11.848,5.719) W29(-11.848,6.369) W30(-11.848,7.019) W31(-11.848,7.669) W32(-11.848,8.32) W34(-11.934,9.365) Y4(-10.984,-9.69) Y5(-11.086,-8.617) Y6(-11.086,-7.967) Y7(-11.086,-7.317) Y8(-11.086,-6.668) Y10(-11.086,-5.753) Y24(-11.392,3.679) Y25(-10.937,4.142) Y26(-11.392,4.606) Y27(-10.937,5.069) Y28(-10.937,5.719) Y29(-10.937,6.369) Y30(-10.937,7.019) Y31(-10.937,7.669) Y32(-10.937,8.32) Y33(-11.327,9.04) Y35(-11.327,10.245)
  oval 0.33x0.254 smd: A8(-22.315,-6.915) A22(-22.315,1.883) A24(-22.315,3.184) A26(-22.315,4.4) A28(-22.315,5.701) A30(-22.315,6.917) B6(-21.665,-8.216) B7(-21.99,-7.565) B8(-21.665,-6.915) B9(-21.895,-6.305) B21(-21.895,1.275) B22(-21.665,1.883) B23(-21.99,2.534) B24(-21.665,3.184) B25(-21.895,3.792) B26(-21.665,4.4) B27(-21.99,5.051) B28(-21.665,5.701) B29(-21.895,6.309) B30(-21.665,6.917) B31(-21.99,7.568) B32(-21.665,8.218) C6(-21.015,-8.216) C7(-21.34,-7.565) C8(-21.021,-6.999) C22(-21.015,1.883) C23(-21.34,2.534) C24(-21.015,3.184) C26(-21.015,4.4) C27(-21.34,5.051) C28(-21.015,5.701) C30(-21.015,6.917) C31(-21.34,7.568) C32(-21.015,8.218) CN6(21.015,-8.216) CN7(21.34,-7.565) CN8(21.021,-6.999) CN10(21.021,-5.61) CN11(21.34,-5.044) CN12(21.021,-4.478) CN14(21.021,-3.088) CN15(21.34,-2.522) CN16(21.021,-1.956) CN18(21.021,-0.566) CN19(21.34,0) CN20(21.021,0.566) CN22(21.021,1.956) CN23(21.34,2.522) CN24(21.021,3.088) CN27(21.34,5.044) CN28(21.021,5.61) CN30(21.014,6.912) CN31(21.461,7.605) CN32(21.014,8.219) CP6(21.665,-8.216) CP7(21.99,-7.565) CP8(21.665,-6.915) CP9(21.895,-6.305) CP10(21.665,-5.694) CP11(21.99,-5.044) CP12(21.665,-4.393) CP13(21.895,-3.783) CP14(21.665,-3.172) CP15(21.99,-2.522) CP16(21.665,-1.871) CP17(21.895,-1.261) CP18(21.665,-0.65) CP19(21.99,0) CP20(21.665,0.65) CP21(21.895,1.261) CP22(21.665,1.871) CP23(21.99,2.522) CP24(21.665,3.172) CP25(21.895,3.783) CP26(21.665,4.393) CP27(21.99,5.044) CP28(21.665,5.694) CP29(21.895,6.305) CP30(21.669,6.983) CP31(22.19,7.605) CP32(21.665,8.296) CR8(22.315,-6.915) CR10(22.315,-5.694) CR12(22.315,-4.393) CR14(22.315,-3.172) CR16(22.315,-1.871) CR18(22.315,-0.65) CR20(22.315,0.65) CR22(22.315,1.871) CR24(22.315,3.172) CR26(22.315,4.393) CR28(22.315,5.694) CR30(22.315,6.912)
  round 0.406 smd: A11(-22.315,-5.322) A12(-22.315,-4.38) A14(-22.315,-3.438) A15(-22.315,-2.496) A17(-22.315,-1.554) A18(-22.315,-0.613) A20(-22.315,0.329) B11(-21.665,-5.322) B12(-21.665,-4.38) B14(-21.665,-3.438) B15(-21.665,-2.496) B17(-21.665,-1.554) B18(-21.665,-0.613) B20(-21.665,0.329) C11(-21.015,-5.322) C12(-21.015,-4.38) C14(-21.015,-3.438) C15(-21.015,-2.496) C17(-21.015,-1.554) C18(-21.015,-0.613) C20(-21.015,0.329) D11(-20.365,-5.322) D12(-20.365,-4.38) D14(-20.365,-3.438) D15(-20.365,-2.496) D17(-20.365,-1.554) D18(-20.365,-0.613) D20(-20.365,0.329) F11(-19.715,-5.322) F12(-19.715,-4.38) F14(-19.715,-3.438) F15(-19.715,-2.496) F17(-19.715,-1.554) F18(-19.715,-0.613) F20(-19.715,0.329) G11(-19.065,-5.322) G12(-19.065,-4.38) G14(-19.065,-3.438) G15(-19.065,-2.496) G17(-19.065,-1.554) G18(-19.065,-0.613) G20(-19.065,0.329) H11(-18.415,-5.322) H12(-18.415,-4.38) H14(-18.415,-3.438) H15(-18.415,-2.496) H17(-18.415,-1.554) H18(-18.415,-0.613) H20(-18.415,0.329) J11(-17.765,-5.322) J12(-17.765,-4.38) J14(-17.765,-3.438) J15(-17.765,-2.496) J17(-17.765,-1.554) J18(-17.765,-0.613) J20(-17.765,0.329)
  oval 0.254x0.33 smd: AA1(-10.421,-11.315) AA2(-10.421,-10.665) AA3(-10.421,-10.015) AA35(-10.719,10.015) AA36(-10.719,10.665) AA37(-10.719,11.315) AB2(-9.763,-10.99) AB35(-10.068,10.34) AB36(-10.068,10.99) AC1(-9.106,-11.315) AC2(-9.106,-10.665) AC3(-9.106,-10.015) AC35(-9.417,10.015) AC36(-9.417,10.665) AC37(-9.417,11.315) AD3(-8.543,-10.34) AD36(-8.809,10.895) AE1(-7.98,-11.315) AE2(-7.98,-10.665) AE3(-7.98,-10.015) AE35(-8.202,10.015) AE36(-8.202,10.665) AE37(-8.202,11.315) AF2(-7.322,-10.99) AF35(-7.551,10.34) AF36(-7.551,10.99) AG1(-6.665,-11.315) AG2(-6.665,-10.665) AG3(-6.665,-10.015) AG35(-6.9,10.015) AG36(-6.9,10.665) AG37(-6.9,11.315) AH3(-6.102,-10.34) AH36(-6.293,10.895) AJ1(-5.539,-11.315) AJ2(-5.539,-10.665) AJ3(-5.539,-10.015) AJ35(-5.685,10.015) AJ36(-5.685,10.665) AJ37(-5.685,11.315) AK2(-4.882,-10.99) AK35(-5.034,10.34) AK36(-5.034,10.99) AL1(-4.224,-11.315) AL2(-4.224,-10.665) AL3(-4.224,-10.015) AL35(-4.383,10.015) AL36(-4.383,10.665) AL37(-4.383,11.315) AM3(-3.661,-10.34) AM36(-3.775,10.895) AN1(-3.098,-11.315) AN2(-3.098,-10.665) AN3(-3.098,-10.015) AN35(-3.168,10.015) AN36(-3.168,10.665) AN37(-3.168,11.315) AP2(-2.441,-10.99) AP35(-2.517,10.34) AP36(-2.517,10.99) AR1(-1.783,-11.315) AR2(-1.783,-10.665) AR3(-1.783,-10.015) AR35(-1.866,10.015) AR36(-1.866,10.665) AR37(-1.866,11.315) AT3(-1.22,-10.34) AT36(-1.259,10.895) AU1(-0.657,-11.315) AU2(-0.657,-10.665) AU3(-0.657,-10.015) AU35(-0.65,10.015) AU36(-0.65,10.665) AU37(-0.65,11.315) AV2(0,-10.99) AV35(0,10.34) AV36(0,10.99) AW1(0.657,-11.315) AW2(0.657,-10.665) AW3(0.657,-10.015) AW35(0.65,10.015) AW36(0.65,10.665) AW37(0.65,11.315) AY3(1.22,-10.34) AY36(1.259,10.895) BA1(1.783,-11.315) BA2(1.783,-10.665) BA3(1.783,-10.015) BA35(1.866,10.015) BA36(1.866,10.665) BA37(1.866,11.315) BB2(2.441,-10.99) BB35(2.517,10.34) BB36(2.517,10.99) BC1(3.098,-11.315) BC2(3.098,-10.665) BC3(3.098,-10.015) BC35(3.168,10.015) BC36(3.168,10.665) BC37(3.168,11.315) BD3(3.661,-10.34) BD36(3.775,10.895) BE1(4.224,-11.315) BE2(4.224,-10.665) BE3(4.224,-10.015) BE35(4.383,10.015) BE36(4.383,10.665) BE37(4.383,11.315) BF2(4.882,-10.99) BF35(5.034,10.34) BF36(5.034,10.99) BG1(5.539,-11.315) BG2(5.539,-10.665) BG3(5.539,-10.015) BG35(5.685,10.015) BG36(5.685,10.665) BG37(5.685,11.315) BH3(6.102,-10.34) BH36(6.293,10.895) BJ1(6.665,-11.315) BJ2(6.665,-10.665) BJ3(6.665,-10.015) BJ35(6.9,10.015) BJ36(6.9,10.665) BJ37(6.9,11.315) BK2(7.322,-10.99) BK35(7.551,10.34) BK36(7.551,10.99) BL1(7.98,-11.315) BL2(7.98,-10.665) BL3(7.98,-10.015) BL35(8.202,10.015) BL36(8.202,10.665) BL37(8.202,11.315) BM3(8.543,-10.34) BM36(8.809,10.895) BN1(9.106,-11.315) BN2(9.106,-10.665) BN3(9.106,-10.015) BN35(9.417,10.015) BN36(9.417,10.665) BN37(9.417,11.315) BP2(9.763,-10.99) BP35(10.068,10.34) BP36(10.068,10.99) BR1(10.421,-11.315) BR2(10.421,-10.665) BR3(10.421,-10.015) BR35(10.719,10.015) BR36(10.719,10.665) BR37(10.719,11.315) BT3(10.984,-10.34) BT36(11.327,10.895) BU1(11.547,-11.315) BU2(11.547,-10.665) BU3(11.547,-10.015) BU35(11.934,10.015) BU36(11.934,10.665) BU37(11.934,11.315) BV2(12.204,-10.99) BV35(12.585,10.34) BV36(12.585,10.99) BW1(12.861,-11.315) BW2(12.861,-10.665) BW3(12.861,-10.015) BW35(13.236,10.015) BW36(13.236,10.665) BW37(13.236,11.315) BY3(13.424,-10.34) BY36(13.844,10.895) CA1(13.988,-11.315) CA2(13.988,-10.665) CA3(13.988,-10.015) CA35(14.451,10.015) CA36(14.451,10.665) CA37(14.451,11.315) CB2(14.645,-10.99) CB35(15.102,10.34) CB36(15.102,10.99) CC1(15.302,-11.315) CC2(15.302,-10.665) CC3(15.302,-10.015) CC35(15.753,10.015) CC36(15.753,10.665) CC37(15.753,11.315) CD3(15.865,-10.34) CE1(16.428,-11.315) CE2(16.428,-10.665) CE3(16.428,-10.015) CE36(16.36,10.895) CF2(17.086,-10.99) CF35(16.968,10.015) CF36(16.968,10.665) CF37(16.968,11.315) CG1(17.743,-11.315) CG2(17.743,-10.665) CG3(17.743,-10.015) CG35(17.619,10.34) CG36(17.619,10.99) CH3(18.306,-10.34) CH35(18.27,10.015) CH36(18.27,10.665) CH37(18.27,11.315) CJ1(18.869,-11.315) CJ2(18.869,-10.665) CJ3(18.869,-10.015) CJ36(18.878,10.895) CK2(19.555,-10.485) CN26(21.021,4.478) G2(-18.869,-10.665) G3(-18.869,-10.015) G36(-18.878,10.895) H3(-18.306,-10.34) H35(-18.27,10.015) H36(-18.27,10.665) H37(-18.27,11.315) J1(-17.743,-11.315) J2(-17.743,-10.665) J3(-17.743,-10.015) J35(-17.619,10.34) J36(-17.619,10.99) K2(-17.086,-10.99) K35(-16.968,10.015) K36(-16.968,10.665) K37(-16.968,11.315) L1(-16.428,-11.315) L2(-16.428,-10.665) L3(-16.428,-10.015) L36(-16.36,10.895) M3(-15.865,-10.34) N1(-15.302,-11.315) N2(-15.302,-10.665) N3(-15.302,-10.015) N35(-15.753,10.015) N36(-15.753,10.665) N37(-15.753,11.315) P2(-14.645,-10.99) P35(-15.102,10.34) P36(-15.102,10.99) R1(-13.988,-11.315) R2(-13.988,-10.665) R3(-13.988,-10.015) R35(-14.451,10.015) R36(-14.451,10.665) R37(-14.451,11.315) T3(-13.424,-10.34) T36(-13.844,10.895) U1(-12.861,-11.315) U2(-12.861,-10.665) U3(-12.861,-10.015) U35(-13.236,10.015) U36(-13.236,10.665) U37(-13.236,11.315) V2(-12.204,-10.99) V35(-12.585,10.34) V36(-12.585,10.99) W1(-11.547,-11.315) W2(-11.547,-10.665) W3(-11.547,-10.015) W35(-11.934,10.015) W36(-11.934,10.665) W37(-11.934,11.315) Y3(-10.984,-10.34) Y36(-11.327,10.895)
